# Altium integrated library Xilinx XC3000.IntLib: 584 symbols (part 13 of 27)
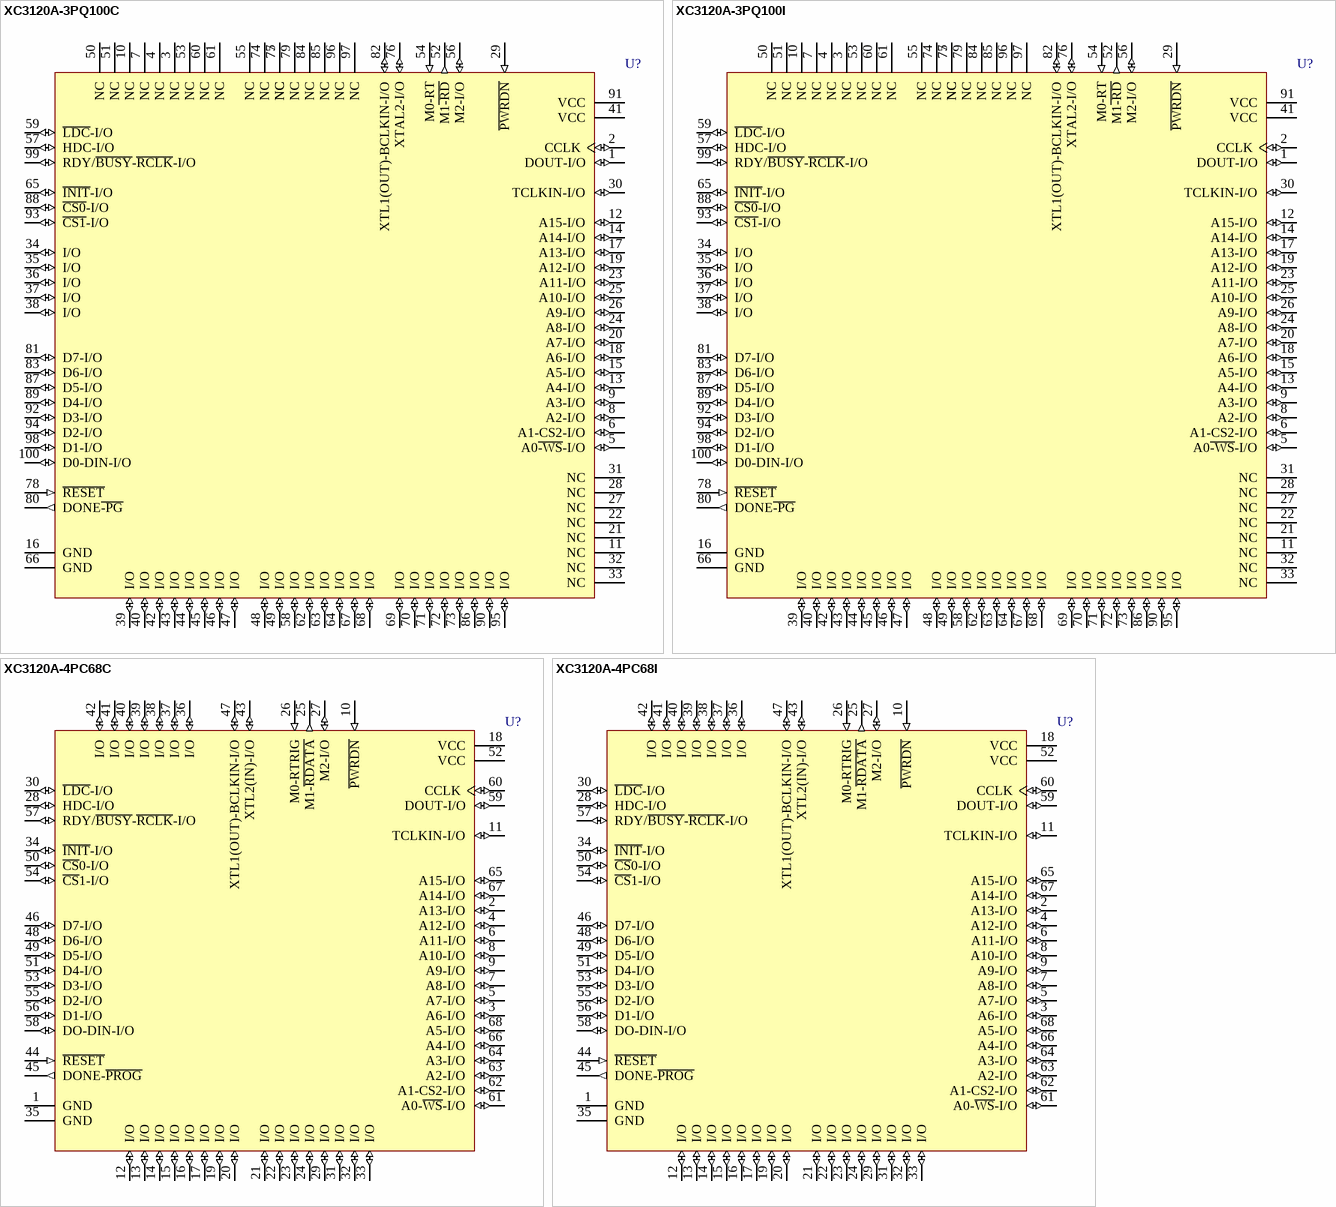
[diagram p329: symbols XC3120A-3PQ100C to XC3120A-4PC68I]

## XC3120A-4PC68C
designator U?
Logic Cell Array with 64 CLBs, with 58 I/O Pins, 68-Pin PLCC, Commercial Grade; ComponentAvailability: Not for New Design
footprint PC68_N (Leaded Chip Carrier, 68-Leads, Body 24x24mm, Pitch 1.27mm, IPC Medium Density)
footprint PC68_L (Leaded Chip Carrier, 68-Leads, Body 24x24mm, Pitch 1.27mm, IPC High Density)
footprint PC68_M (Leaded Chip Carrier, 68-Leads, Body 24x24mm, Pitch 1.27mm, IPC Low Density)
3D model XC3120A-PC68 (68-Pin Plastic Leaded Chip Carrier (PC68))
pins: 1 GND (power), 2 A13-I/O (io), 3 A6-I/O (io), 4 A12-I/O (io), 5 A7-I/O (io), 6 A11-I/O (io), 7 A8-I/O (io), 8 A10-I/O (io), 9 A9-I/O (io), 10 ~{PWRDN} (in), 11 TCLKIN-I/O (io), 12 I/O (io), 13 I/O (io), 14 I/O (io), 15 I/O (io), 16 I/O (io), 17 I/O (io), 18 VCC (power), 19 I/O (io), 20 I/O (io), 21 I/O (io), 22 I/O (io), 23 I/O (io), 24 I/O (io), 25 M1-~{RDATA} (out), 26 M0-RTRIG (in), 27 M2-I/O (io), 28 HDC-I/O (io), 29 I/O (io), 30 ~{LDC}-I/O (io), 31 I/O (io), 32 I/O (io), 33 I/O (io), 34 ~{INIT}-I/O (io), 35 GND (power), 36 I/O (io), 37 I/O (io), 38 I/O (io), 39 I/O (io), 40 I/O (io), 41 I/O (io), 42 I/O (io), 43 XTL2(IN)-I/O (io), 44 ~{RESET} (in), 45 DONE-~{PROG} (out), 46 D7-I/O (io), 47 XTL1(OUT)-BCLKIN-I/O (io), 48 D6-I/O (io), 49 D5-I/O (io), 50 ~{CS}0-I/O (io), 51 D4-I/O (io), 52 VCC (power), 53 D3-I/O (io), 54 ~{CS}1-I/O (io), 55 D2-I/O (io), 56 D1-I/O (io), 57 RDY/~{BUSY}-~{RCLK}-I/O (io), 58 DO-DIN-I/O (io), 59 DOUT-I/O (io), 60 CCLK (io), 61 A0-~{WS}-I/O (io), 62 A1-CS2-I/O (io), 63 A2-I/O (io), 64 A3-I/O (io), 65 A15-I/O (io), 66 A4-I/O (io), 67 A14-I/O (io), 68 A5-I/O (io)

## XC3120A-4PC68I
designator U?
Logic Cell Array with 64 CLBs, with 58 I/O Pins, 68-Pin PLCC, Industrial Grade; ComponentAvailability: Not for New Design
footprint PC68_N (Leaded Chip Carrier, 68-Leads, Body 24x24mm, Pitch 1.27mm, IPC Medium Density)
footprint PC68_L (Leaded Chip Carrier, 68-Leads, Body 24x24mm, Pitch 1.27mm, IPC High Density)
footprint PC68_M (Leaded Chip Carrier, 68-Leads, Body 24x24mm, Pitch 1.27mm, IPC Low Density)
3D model XC3120A-PC68 (68-Pin Plastic Leaded Chip Carrier (PC68))
pins: 1 GND (power), 2 A13-I/O (io), 3 A6-I/O (io), 4 A12-I/O (io), 5 A7-I/O (io), 6 A11-I/O (io), 7 A8-I/O (io), 8 A10-I/O (io), 9 A9-I/O (io), 10 ~{PWRDN} (in), 11 TCLKIN-I/O (io), 12 I/O (io), 13 I/O (io), 14 I/O (io), 15 I/O (io), 16 I/O (io), 17 I/O (io), 18 VCC (power), 19 I/O (io), 20 I/O (io), 21 I/O (io), 22 I/O (io), 23 I/O (io), 24 I/O (io), 25 M1-~{RDATA} (out), 26 M0-RTRIG (in), 27 M2-I/O (io), 28 HDC-I/O (io), 29 I/O (io), 30 ~{LDC}-I/O (io), 31 I/O (io), 32 I/O (io), 33 I/O (io), 34 ~{INIT}-I/O (io), 35 GND (power), 36 I/O (io), 37 I/O (io), 38 I/O (io), 39 I/O (io), 40 I/O (io), 41 I/O (io), 42 I/O (io), 43 XTL2(IN)-I/O (io), 44 ~{RESET} (in), 45 DONE-~{PROG} (out), 46 D7-I/O (io), 47 XTL1(OUT)-BCLKIN-I/O (io), 48 D6-I/O (io), 49 D5-I/O (io), 50 ~{CS}0-I/O (io), 51 D4-I/O (io), 52 VCC (power), 53 D3-I/O (io), 54 ~{CS}1-I/O (io), 55 D2-I/O (io), 56 D1-I/O (io), 57 RDY/~{BUSY}-~{RCLK}-I/O (io), 58 DO-DIN-I/O (io), 59 DOUT-I/O (io), 60 CCLK (io), 61 A0-~{WS}-I/O (io), 62 A1-CS2-I/O (io), 63 A2-I/O (io), 64 A3-I/O (io), 65 A15-I/O (io), 66 A4-I/O (io), 67 A14-I/O (io), 68 A5-I/O (io)

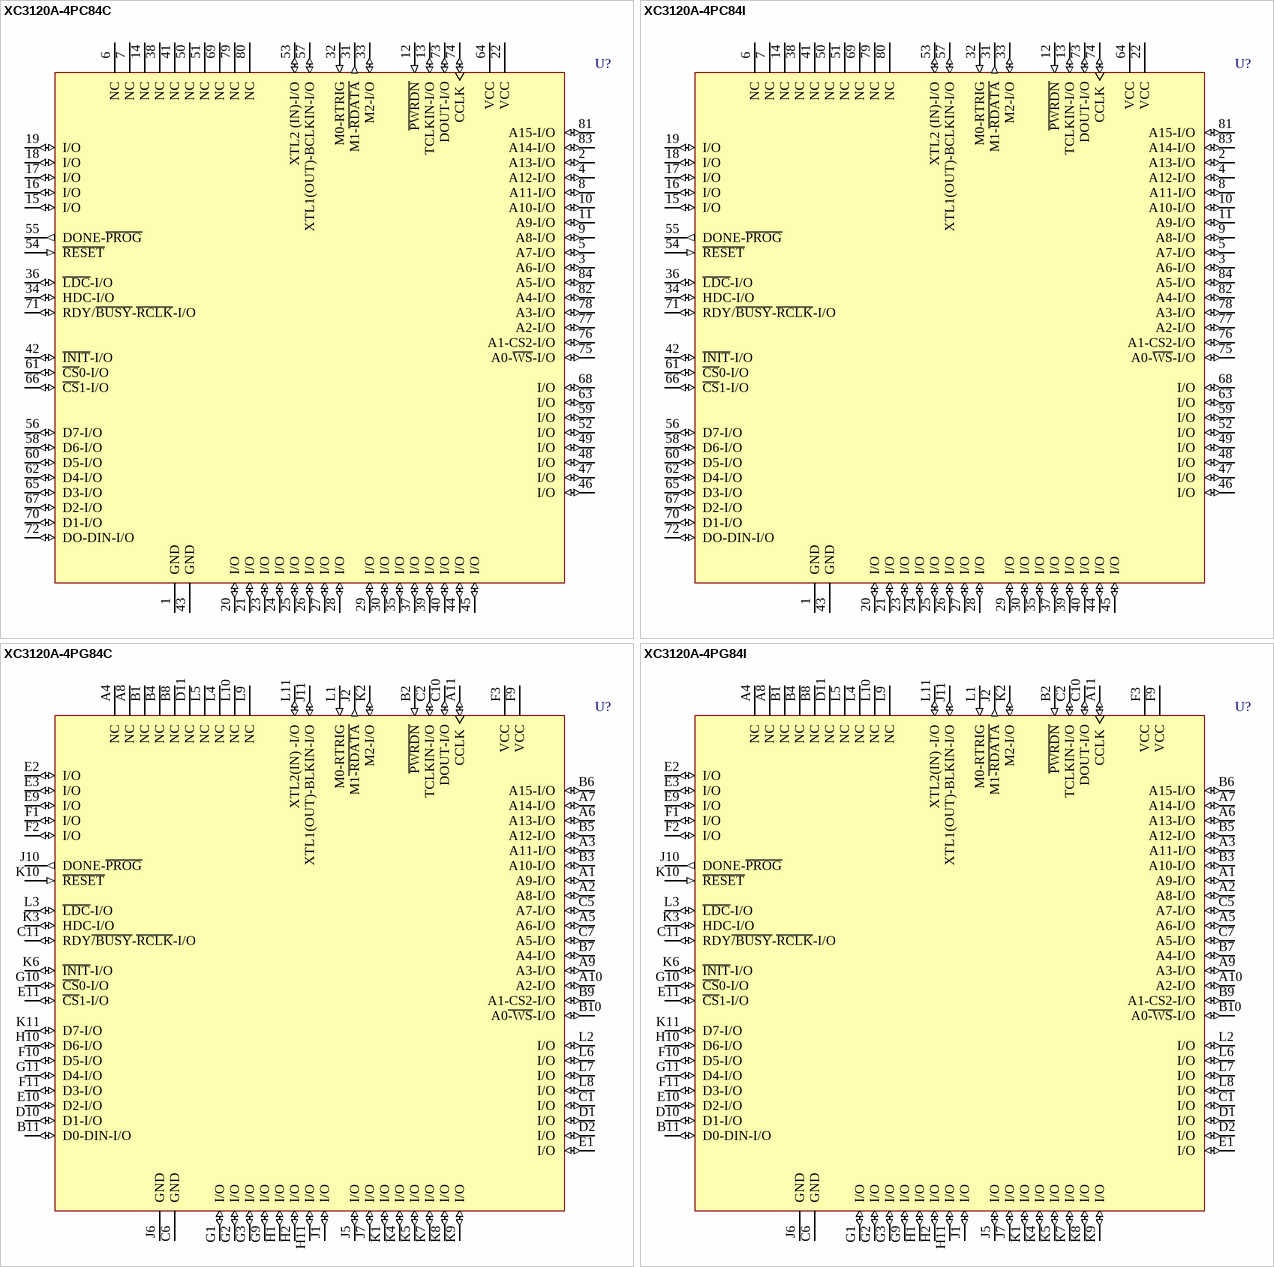
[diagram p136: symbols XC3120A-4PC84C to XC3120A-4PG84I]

## XC3120A-4PC84C
designator U?
Logic Cell Array with 64 CLBs, with 64 I/O Pins, 84-Pin PLCC, Commercial Grade; ComponentAvailability: Not for New Design
footprint PC84_N (Leaded Chip Carrier, 84-Leads, Body 29.3x29.3mm, Pitch 1.27mm, IPC Medium Density)
footprint PC84_L (Leaded Chip Carrier, 84-Leads, Body 29.3x29.3mm, Pitch 1.27mm, IPC High Density)
footprint PC84_M (Leaded Chip Carrier, 84-Leads, Body 29.3x29.3mm, Pitch 1.27mm, IPC Low Density)
3D model XC3120A-PC84 (84-Pin Plastic Leaded Chip Carrier (PC84))
pins: 1 GND (power), 2 A13-I/O (io), 3 A6-I/O (io), 4 A12-I/O (io), 5 A7-I/O (io), 6 NC, 7 NC, 8 A11-I/O (io), 9 A8-I/O (io), 10 A10-I/O (io), 11 A9-I/O (io), 12 ~{PWRDN} (in), 13 TCLKIN-I/O (io), 14 NC, 15 I/O (io), 16 I/O (io), 17 I/O (io), 18 I/O (io), 19 I/O (io), 20 I/O (io), 21 I/O (io), 22 VCC (power), 23 I/O (io), 24 I/O (io), 25 I/O (io), 26 I/O (io), 27 I/O (io), 28 I/O (io), 29 I/O (io), 30 I/O (io), 31 M1-~{RDATA} (out), 32 M0-RTRIG (in), 33 M2-I/O (io), 34 HDC-I/O (io), 35 I/O (io), 36 ~{LDC}-I/O (io), 37 I/O (io), 38 NC, 39 I/O (io), 40 I/O (io), 41 NC, 42 ~{INIT}-I/O (io), 43 GND (power), 44 I/O (io), 45 I/O (io), 46 I/O (io), 47 I/O (io), 48 I/O (io), 49 I/O (io), 50 NC, 51 NC, 52 I/O (io), 53 XTL2 (IN)-I/O (io), 54 ~{RESET} (in), 55 DONE-~{PROG} (out), 56 D7-I/O (io), 57 XTL1(OUT)-BCLKIN-I/O (io), 58 D6-I/O (io), 59 I/O (io), 60 D5-I/O (io), 61 ~{CS}0-I/O (io), 62 D4-I/O (io), 63 I/O (io), 64 VCC (power), 65 D3-I/O (io), 66 ~{CS}1-I/O (io), 67 D2-I/O (io), 68 I/O (io), 69 NC, 70 D1-I/O (io), 71 RDY/~{BUSY}-~{RCLK}-I/O (io), 72 DO-DIN-I/O (io), 73 DOUT-I/O (io), 74 CCLK (io), 75 A0-~{WS}-I/O (io), 76 A1-CS2-I/O (io), 77 A2-I/O (io), 78 A3-I/O (io), 79 NC, 80 NC, 81 A15-I/O (io), 82 A4-I/O (io), 83 A14-I/O (io), 84 A5-I/O (io)

## XC3120A-4PC84I
designator U?
Logic Cell Array with 64 CLBs, with 64 I/O Pins, 84-Pin PLCC, Industrial Grade; ComponentAvailability: Not for New Design
footprint PC84_N (Leaded Chip Carrier, 84-Leads, Body 29.3x29.3mm, Pitch 1.27mm, IPC Medium Density)
footprint PC84_L (Leaded Chip Carrier, 84-Leads, Body 29.3x29.3mm, Pitch 1.27mm, IPC High Density)
footprint PC84_M (Leaded Chip Carrier, 84-Leads, Body 29.3x29.3mm, Pitch 1.27mm, IPC Low Density)
3D model XC3120A-PC84 (84-Pin Plastic Leaded Chip Carrier (PC84))
pins: 1 GND (power), 2 A13-I/O (io), 3 A6-I/O (io), 4 A12-I/O (io), 5 A7-I/O (io), 6 NC, 7 NC, 8 A11-I/O (io), 9 A8-I/O (io), 10 A10-I/O (io), 11 A9-I/O (io), 12 ~{PWRDN} (in), 13 TCLKIN-I/O (io), 14 NC, 15 I/O (io), 16 I/O (io), 17 I/O (io), 18 I/O (io), 19 I/O (io), 20 I/O (io), 21 I/O (io), 22 VCC (power), 23 I/O (io), 24 I/O (io), 25 I/O (io), 26 I/O (io), 27 I/O (io), 28 I/O (io), 29 I/O (io), 30 I/O (io), 31 M1-~{RDATA} (out), 32 M0-RTRIG (in), 33 M2-I/O (io), 34 HDC-I/O (io), 35 I/O (io), 36 ~{LDC}-I/O (io), 37 I/O (io), 38 NC, 39 I/O (io), 40 I/O (io), 41 NC, 42 ~{INIT}-I/O (io), 43 GND (power), 44 I/O (io), 45 I/O (io), 46 I/O (io), 47 I/O (io), 48 I/O (io), 49 I/O (io), 50 NC, 51 NC, 52 I/O (io), 53 XTL2 (IN)-I/O (io), 54 ~{RESET} (in), 55 DONE-~{PROG} (out), 56 D7-I/O (io), 57 XTL1(OUT)-BCLKIN-I/O (io), 58 D6-I/O (io), 59 I/O (io), 60 D5-I/O (io), 61 ~{CS}0-I/O (io), 62 D4-I/O (io), 63 I/O (io), 64 VCC (power), 65 D3-I/O (io), 66 ~{CS}1-I/O (io), 67 D2-I/O (io), 68 I/O (io), 69 NC, 70 D1-I/O (io), 71 RDY/~{BUSY}-~{RCLK}-I/O (io), 72 DO-DIN-I/O (io), 73 DOUT-I/O (io), 74 CCLK (io), 75 A0-~{WS}-I/O (io), 76 A1-CS2-I/O (io), 77 A2-I/O (io), 78 A3-I/O (io), 79 NC, 80 NC, 81 A15-I/O (io), 82 A4-I/O (io), 83 A14-I/O (io), 84 A5-I/O (io)

## XC3120A-4PG84C
designator U?
Logic Cell Array with 64 CLBs, with 64 I/O Pins, 84-Pin PGA, Commercial Grade; ComponentAvailability: Not for New Design
footprint PG84 (PGA, 85-Leads, Body 28x28mm, Pitch 2.54mm)
3D model XC3120A-PG84 (84-Pin Ceramic Pin Grid Array (PG84))
pins: A1 A9-I/O (io), A2 A8-I/O (io), A3 A11-I/O (io), A4 NC, A5 A6-I/O (io), A6 A13-I/O (io), A7 A14-I/O (io), A8 NC, A9 A3-I/O (io), A10 A2-I/O (io), A11 CCLK (io), B1 NC, B2 ~{PWRDN} (in), B3 A10-I/O (io), B4 NC, B5 A12-I/O (io), B6 A15-I/O (io), B7 A4-I/O (io), B8 NC, B9 A1-CS2-I/O (io), B10 A0~{-WS}-I/O (io), B11 D0-DIN-I/O (io), C1 I/O (io), C2 TCLKIN-I/O (io), C5 A7-I/O (io), C6 GND (power), C7 A5-I/O (io), C10 DOUT-I/O (io), C11 RDY~{/BUSY}-~{RCLK}-I/O (io), D1 I/O (io), D2 I/O (io), D10 D1-I/O (io), D11 NC, E1 I/O (io), E2 I/O (io), E3 I/O (io), E9 I/O (io), E10 D2-I/O (io), E11 ~{CS}1-I/O (io), F1 I/O (io), F2 I/O (io), F3 VCC (power), F9 VCC (power), F10 D5-I/O (io), F11 D3-I/O (io), G1 I/O (io), G2 I/O (io), G3 I/O (io), G9 I/O (io), G10 ~{CS}0-I/O (io), G11 D4-I/O (io), H1 I/O (io), H2 I/O (io), H10 D6-I/O (io), H11 I/O (io), J1 I/O (io), J2 M1~{-RDATA} (out), J5 I/O (io), J6 GND (power), J7 I/O (io), J10 DONE-~{PROG} (out), J11 XTL1(OUT)-BLKIN-I/O (io), K1 I/O (io), K2 M2-I/O (io), K3 HDC-I/O (io), K4 I/O (io), K5 I/O (io), K6 ~{INIT}-I/O (io), K7 I/O (io), K8 I/O (io), K9 I/O (io), K10 ~{RESET} (in), K11 D7-I/O (io), L1 M0-RTRIG (in), L2 I/O (io), L3 ~{LDC}-I/O (io), L4 NC, L5 NC, L6 I/O (io), L7 I/O (io), L8 I/O (io), L9 NC, L10 NC, L11 XTL2(IN) -I/O (io)

## XC3120A-4PG84I
designator U?
Logic Cell Array with 64 CLBs, with 64 I/O Pins, 84-Pin PGA, Industrial Grade; ComponentAvailability: Not for New Design
footprint PG84 (PGA, 85-Leads, Body 28x28mm, Pitch 2.54mm)
3D model XC3120A-PG84 (84-Pin Ceramic Pin Grid Array (PG84))
pins: A1 A9-I/O (io), A2 A8-I/O (io), A3 A11-I/O (io), A4 NC, A5 A6-I/O (io), A6 A13-I/O (io), A7 A14-I/O (io), A8 NC, A9 A3-I/O (io), A10 A2-I/O (io), A11 CCLK (io), B1 NC, B2 ~{PWRDN} (in), B3 A10-I/O (io), B4 NC, B5 A12-I/O (io), B6 A15-I/O (io), B7 A4-I/O (io), B8 NC, B9 A1-CS2-I/O (io), B10 A0~{-WS}-I/O (io), B11 D0-DIN-I/O (io), C1 I/O (io), C2 TCLKIN-I/O (io), C5 A7-I/O (io), C6 GND (power), C7 A5-I/O (io), C10 DOUT-I/O (io), C11 RDY~{/BUSY}-~{RCLK}-I/O (io), D1 I/O (io), D2 I/O (io), D10 D1-I/O (io), D11 NC, E1 I/O (io), E2 I/O (io), E3 I/O (io), E9 I/O (io), E10 D2-I/O (io), E11 ~{CS}1-I/O (io), F1 I/O (io), F2 I/O (io), F3 VCC (power), F9 VCC (power), F10 D5-I/O (io), F11 D3-I/O (io), G1 I/O (io), G2 I/O (io), G3 I/O (io), G9 I/O (io), G10 ~{CS}0-I/O (io), G11 D4-I/O (io), H1 I/O (io), H2 I/O (io), H10 D6-I/O (io), H11 I/O (io), J1 I/O (io), J2 M1~{-RDATA} (out), J5 I/O (io), J6 GND (power), J7 I/O (io), J10 DONE-~{PROG} (out), J11 XTL1(OUT)-BLKIN-I/O (io), K1 I/O (io), K2 M2-I/O (io), K3 HDC-I/O (io), K4 I/O (io), K5 I/O (io), K6 ~{INIT}-I/O (io), K7 I/O (io), K8 I/O (io), K9 I/O (io), K10 ~{RESET} (in), K11 D7-I/O (io), L1 M0-RTRIG (in), L2 I/O (io), L3 ~{LDC}-I/O (io), L4 NC, L5 NC, L6 I/O (io), L7 I/O (io), L8 I/O (io), L9 NC, L10 NC, L11 XTL2(IN) -I/O (io)

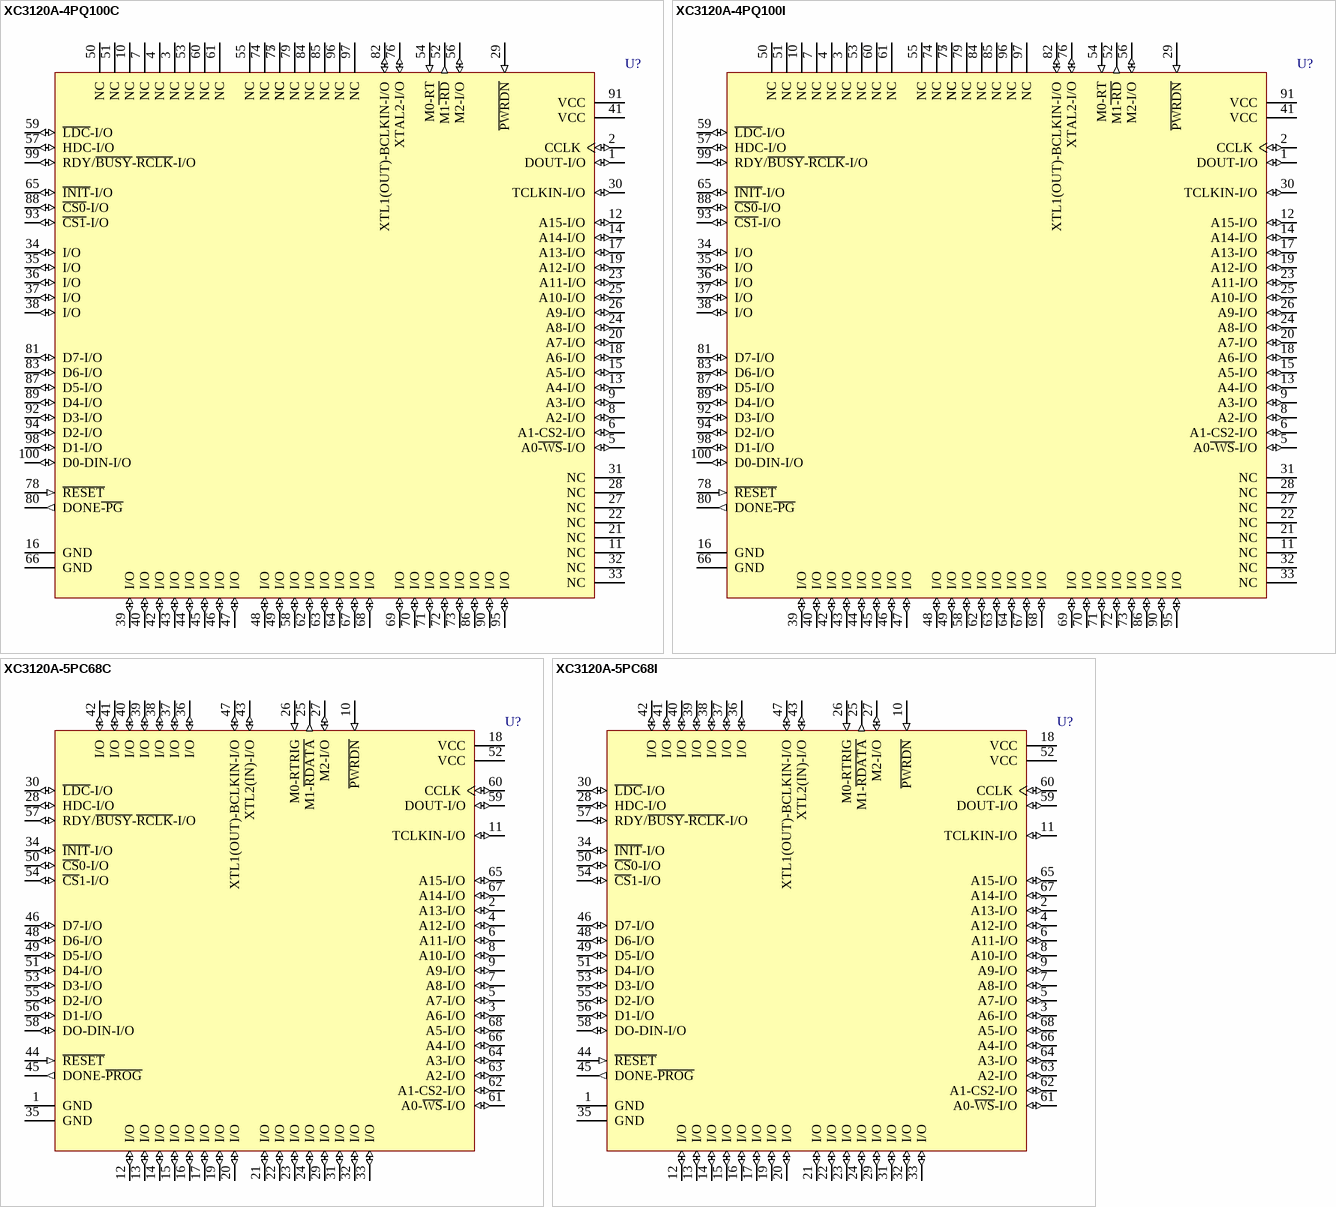
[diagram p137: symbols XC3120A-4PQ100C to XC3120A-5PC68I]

## XC3120A-4PQ100C
designator U?
Logic Cell Array with 64 CLBs, with 64 I/O Pins, 100-Pin PQFP, Commercial Grade; ComponentAvailability: Not for New Design
footprint PQ100_N (QFP, 100-Leads, Body 20x14mm, Pitch 0.65mm, IPC Medium Density)
footprint PQ100_L (QFP, 100-Leads, Body 20x14mm, Pitch 0.65mm, IPC High Density)
footprint PQ100_M (QFP, 100-Leads, Body 20x14mm, Pitch 0.65mm, IPC Low Density)
3D model XC3120A-PQ100 (100-Pin Plastic Quad Flat Pack (PQ100))
pins: 1 DOUT-I/O (io), 2 CCLK (io), 3 NC, 4 NC, 5 A0~{-WS}-I/O (io), 6 A1-CS2-I/O (io), 7 NC, 8 A2-I/O (io), 9 A3-I/O (io), 10 NC, 11 NC, 12 A15-I/O (io), 13 A4-I/O (io), 14 A14-I/O (io), 15 A5-I/O (io), 16 GND (power), 17 A13-I/O (io), 18 A6-I/O (io), 19 A12-I/O (io), 20 A7-I/O (io), 21 NC, 22 NC, 23 A11-I/O (io), 24 A8-I/O (io), 25 A10-I/O (io), 26 A9-I/O (io), 27 NC, 28 NC, 29 ~{PWRDN} (in), 30 TCLKIN-I/O (io), 31 NC, 32 NC, 33 NC, 34 I/O (io), 35 I/O (io), 36 I/O (io), 37 I/O (io), 38 I/O (io), 39 I/O (io), 40 I/O (io), 41 VCC (power), 42 I/O (io), 43 I/O (io), 44 I/O (io), 45 I/O (io), 46 I/O (io), 47 I/O (io), 48 I/O (io), 49 I/O (io), 50 NC, 51 NC, 52 M1~{-RD} (out), 53 NC, 54 M0-RT (in), 55 NC, 56 M2-I/O (io), 57 HDC-I/O (io), 58 I/O (io), 59 ~{LDC}-I/O (io), 60 NC, 61 NC, 62 I/O (io), 63 I/O (io), 64 I/O (io), 65 ~{INIT}-I/O (io), 66 GND (power), 67 I/O (io), 68 I/O (io), 69 I/O (io), 70 I/O (io), 71 I/O (io), 72 I/O (io), 73 I/O (io), 74 NC, 75 NC, 76 XTAL2-I/O (io), 77 NC, 78 ~{RESET} (in), 79 NC, 80 DONE~{-PG} (out), 81 D7-I/O (io), 82 XTL1(OUT)-BCLKIN-I/O (io), 83 D6-I/O (io), 84 NC, 85 NC, 86 I/O (io), 87 D5-I/O (io), 88 ~{CS0}-I/O (io), 89 D4-I/O (io), 90 I/O (io), 91 VCC (power), 92 D3-I/O (io), 93 ~{CS1}-I/O (io), 94 D2-I/O (io), 95 I/O (io), 96 NC, 97 NC, 98 D1-I/O (io), 99 RDY/~{BUSY}-~{RCLK}-I/O (io), 100 D0-DIN-I/O (io)

## XC3120A-4PQ100I
designator U?
Logic Cell Array with 64 CLBs, with 64 I/O Pins, 100-Pin PQFP, Industrial Grade; ComponentAvailability: Not for New Design
footprint PQ100_N (QFP, 100-Leads, Body 20x14mm, Pitch 0.65mm, IPC Medium Density)
footprint PQ100_L (QFP, 100-Leads, Body 20x14mm, Pitch 0.65mm, IPC High Density)
footprint PQ100_M (QFP, 100-Leads, Body 20x14mm, Pitch 0.65mm, IPC Low Density)
3D model XC3120A-PQ100 (100-Pin Plastic Quad Flat Pack (PQ100))
pins: 1 DOUT-I/O (io), 2 CCLK (io), 3 NC, 4 NC, 5 A0~{-WS}-I/O (io), 6 A1-CS2-I/O (io), 7 NC, 8 A2-I/O (io), 9 A3-I/O (io), 10 NC, 11 NC, 12 A15-I/O (io), 13 A4-I/O (io), 14 A14-I/O (io), 15 A5-I/O (io), 16 GND (power), 17 A13-I/O (io), 18 A6-I/O (io), 19 A12-I/O (io), 20 A7-I/O (io), 21 NC, 22 NC, 23 A11-I/O (io), 24 A8-I/O (io), 25 A10-I/O (io), 26 A9-I/O (io), 27 NC, 28 NC, 29 ~{PWRDN} (in), 30 TCLKIN-I/O (io), 31 NC, 32 NC, 33 NC, 34 I/O (io), 35 I/O (io), 36 I/O (io), 37 I/O (io), 38 I/O (io), 39 I/O (io), 40 I/O (io), 41 VCC (power), 42 I/O (io), 43 I/O (io), 44 I/O (io), 45 I/O (io), 46 I/O (io), 47 I/O (io), 48 I/O (io), 49 I/O (io), 50 NC, 51 NC, 52 M1~{-RD} (out), 53 NC, 54 M0-RT (in), 55 NC, 56 M2-I/O (io), 57 HDC-I/O (io), 58 I/O (io), 59 ~{LDC}-I/O (io), 60 NC, 61 NC, 62 I/O (io), 63 I/O (io), 64 I/O (io), 65 ~{INIT}-I/O (io), 66 GND (power), 67 I/O (io), 68 I/O (io), 69 I/O (io), 70 I/O (io), 71 I/O (io), 72 I/O (io), 73 I/O (io), 74 NC, 75 NC, 76 XTAL2-I/O (io), 77 NC, 78 ~{RESET} (in), 79 NC, 80 DONE~{-PG} (out), 81 D7-I/O (io), 82 XTL1(OUT)-BCLKIN-I/O (io), 83 D6-I/O (io), 84 NC, 85 NC, 86 I/O (io), 87 D5-I/O (io), 88 ~{CS0}-I/O (io), 89 D4-I/O (io), 90 I/O (io), 91 VCC (power), 92 D3-I/O (io), 93 ~{CS1}-I/O (io), 94 D2-I/O (io), 95 I/O (io), 96 NC, 97 NC, 98 D1-I/O (io), 99 RDY/~{BUSY}-~{RCLK}-I/O (io), 100 D0-DIN-I/O (io)

## XC3120A-5PC68C
designator U?
Logic Cell Array with 64 CLBs, with 58 I/O Pins, 68-Pin PLCC, Commercial Grade; ComponentAvailability: Not for New Design
footprint PC68_N (Leaded Chip Carrier, 68-Leads, Body 24x24mm, Pitch 1.27mm, IPC Medium Density)
footprint PC68_L (Leaded Chip Carrier, 68-Leads, Body 24x24mm, Pitch 1.27mm, IPC High Density)
footprint PC68_M (Leaded Chip Carrier, 68-Leads, Body 24x24mm, Pitch 1.27mm, IPC Low Density)
3D model XC3120A-PC68 (68-Pin Plastic Leaded Chip Carrier (PC68))
pins: 1 GND (power), 2 A13-I/O (io), 3 A6-I/O (io), 4 A12-I/O (io), 5 A7-I/O (io), 6 A11-I/O (io), 7 A8-I/O (io), 8 A10-I/O (io), 9 A9-I/O (io), 10 ~{PWRDN} (in), 11 TCLKIN-I/O (io), 12 I/O (io), 13 I/O (io), 14 I/O (io), 15 I/O (io), 16 I/O (io), 17 I/O (io), 18 VCC (power), 19 I/O (io), 20 I/O (io), 21 I/O (io), 22 I/O (io), 23 I/O (io), 24 I/O (io), 25 M1-~{RDATA} (out), 26 M0-RTRIG (in), 27 M2-I/O (io), 28 HDC-I/O (io), 29 I/O (io), 30 ~{LDC}-I/O (io), 31 I/O (io), 32 I/O (io), 33 I/O (io), 34 ~{INIT}-I/O (io), 35 GND (power), 36 I/O (io), 37 I/O (io), 38 I/O (io), 39 I/O (io), 40 I/O (io), 41 I/O (io), 42 I/O (io), 43 XTL2(IN)-I/O (io), 44 ~{RESET} (in), 45 DONE-~{PROG} (out), 46 D7-I/O (io), 47 XTL1(OUT)-BCLKIN-I/O (io), 48 D6-I/O (io), 49 D5-I/O (io), 50 ~{CS}0-I/O (io), 51 D4-I/O (io), 52 VCC (power), 53 D3-I/O (io), 54 ~{CS}1-I/O (io), 55 D2-I/O (io), 56 D1-I/O (io), 57 RDY/~{BUSY}-~{RCLK}-I/O (io), 58 DO-DIN-I/O (io), 59 DOUT-I/O (io), 60 CCLK (io), 61 A0-~{WS}-I/O (io), 62 A1-CS2-I/O (io), 63 A2-I/O (io), 64 A3-I/O (io), 65 A15-I/O (io), 66 A4-I/O (io), 67 A14-I/O (io), 68 A5-I/O (io)

## XC3120A-5PC68I
designator U?
Logic Cell Array with 64 CLBs, with 58 I/O Pins, 68-Pin PLCC, Industrial Grade; ComponentAvailability: Not for New Design
footprint PC68_N (Leaded Chip Carrier, 68-Leads, Body 24x24mm, Pitch 1.27mm, IPC Medium Density)
footprint PC68_L (Leaded Chip Carrier, 68-Leads, Body 24x24mm, Pitch 1.27mm, IPC High Density)
footprint PC68_M (Leaded Chip Carrier, 68-Leads, Body 24x24mm, Pitch 1.27mm, IPC Low Density)
3D model XC3120A-PC68 (68-Pin Plastic Leaded Chip Carrier (PC68))
pins: 1 GND (power), 2 A13-I/O (io), 3 A6-I/O (io), 4 A12-I/O (io), 5 A7-I/O (io), 6 A11-I/O (io), 7 A8-I/O (io), 8 A10-I/O (io), 9 A9-I/O (io), 10 ~{PWRDN} (in), 11 TCLKIN-I/O (io), 12 I/O (io), 13 I/O (io), 14 I/O (io), 15 I/O (io), 16 I/O (io), 17 I/O (io), 18 VCC (power), 19 I/O (io), 20 I/O (io), 21 I/O (io), 22 I/O (io), 23 I/O (io), 24 I/O (io), 25 M1-~{RDATA} (out), 26 M0-RTRIG (in), 27 M2-I/O (io), 28 HDC-I/O (io), 29 I/O (io), 30 ~{LDC}-I/O (io), 31 I/O (io), 32 I/O (io), 33 I/O (io), 34 ~{INIT}-I/O (io), 35 GND (power), 36 I/O (io), 37 I/O (io), 38 I/O (io), 39 I/O (io), 40 I/O (io), 41 I/O (io), 42 I/O (io), 43 XTL2(IN)-I/O (io), 44 ~{RESET} (in), 45 DONE-~{PROG} (out), 46 D7-I/O (io), 47 XTL1(OUT)-BCLKIN-I/O (io), 48 D6-I/O (io), 49 D5-I/O (io), 50 ~{CS}0-I/O (io), 51 D4-I/O (io), 52 VCC (power), 53 D3-I/O (io), 54 ~{CS}1-I/O (io), 55 D2-I/O (io), 56 D1-I/O (io), 57 RDY/~{BUSY}-~{RCLK}-I/O (io), 58 DO-DIN-I/O (io), 59 DOUT-I/O (io), 60 CCLK (io), 61 A0-~{WS}-I/O (io), 62 A1-CS2-I/O (io), 63 A2-I/O (io), 64 A3-I/O (io), 65 A15-I/O (io), 66 A4-I/O (io), 67 A14-I/O (io), 68 A5-I/O (io)

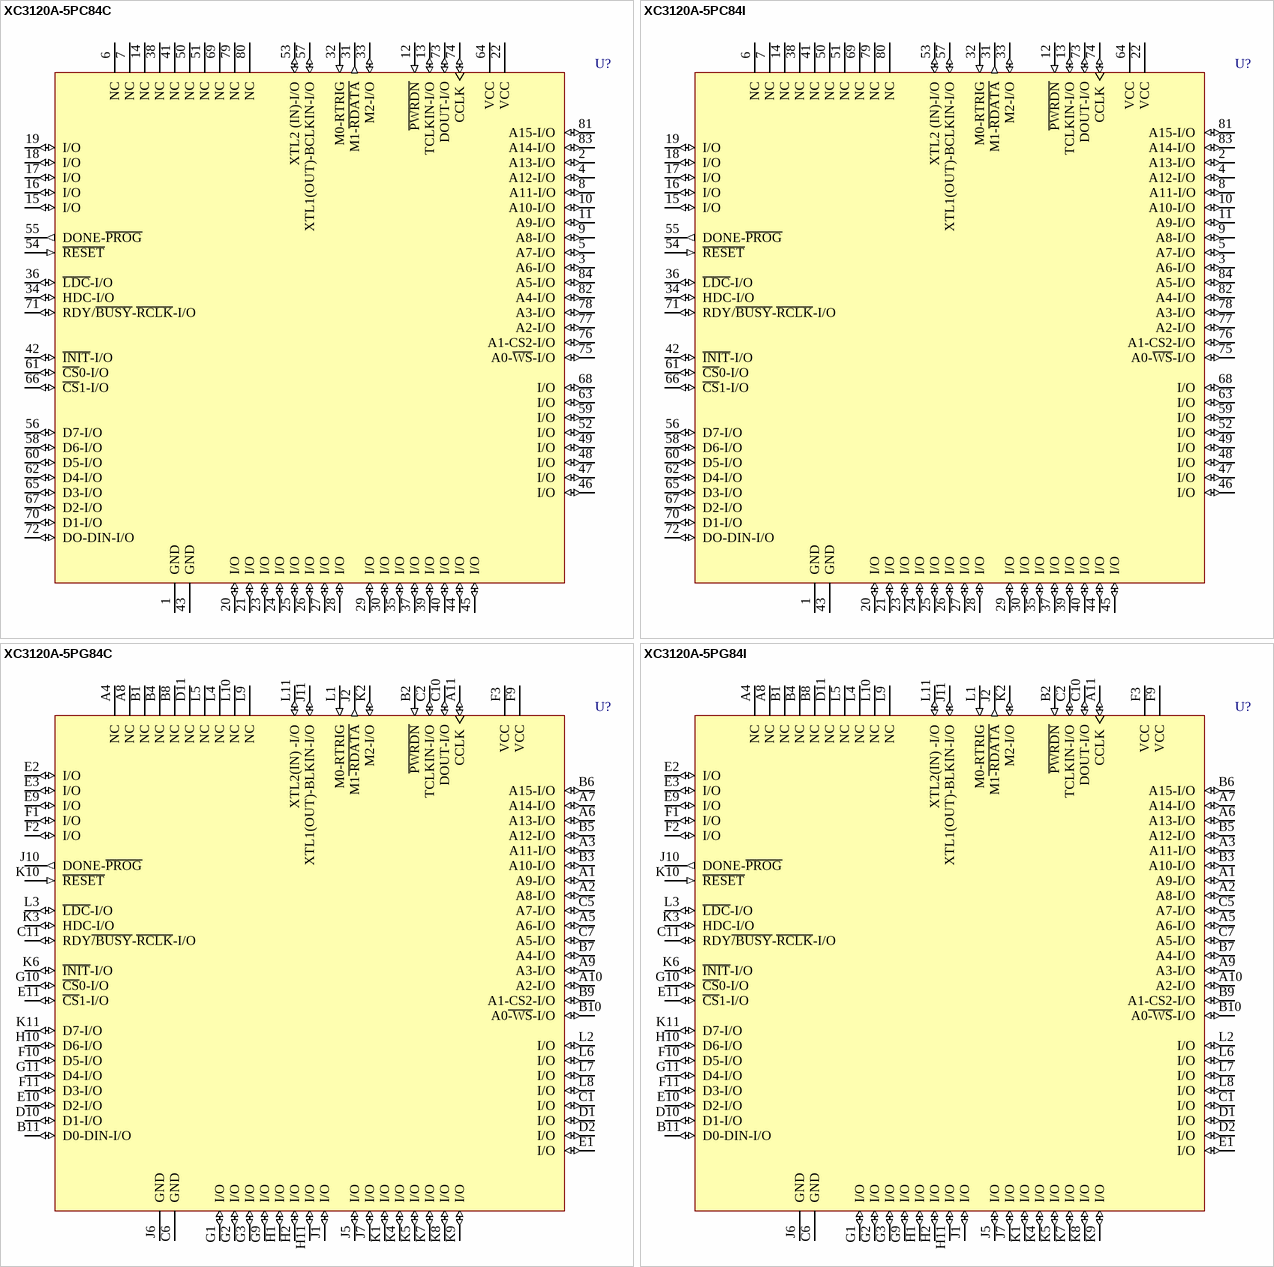
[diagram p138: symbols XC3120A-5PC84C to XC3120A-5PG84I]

## XC3120A-5PC84C
designator U?
Logic Cell Array with 64 CLBs, with 64 I/O Pins, 84-Pin PLCC, Commercial Grade; ComponentAvailability: Not for New Design
footprint PC84_N (Leaded Chip Carrier, 84-Leads, Body 29.3x29.3mm, Pitch 1.27mm, IPC Medium Density)
footprint PC84_L (Leaded Chip Carrier, 84-Leads, Body 29.3x29.3mm, Pitch 1.27mm, IPC High Density)
footprint PC84_M (Leaded Chip Carrier, 84-Leads, Body 29.3x29.3mm, Pitch 1.27mm, IPC Low Density)
3D model XC3120A-PC84 (84-Pin Plastic Leaded Chip Carrier (PC84))
pins: 1 GND (power), 2 A13-I/O (io), 3 A6-I/O (io), 4 A12-I/O (io), 5 A7-I/O (io), 6 NC, 7 NC, 8 A11-I/O (io), 9 A8-I/O (io), 10 A10-I/O (io), 11 A9-I/O (io), 12 ~{PWRDN} (in), 13 TCLKIN-I/O (io), 14 NC, 15 I/O (io), 16 I/O (io), 17 I/O (io), 18 I/O (io), 19 I/O (io), 20 I/O (io), 21 I/O (io), 22 VCC (power), 23 I/O (io), 24 I/O (io), 25 I/O (io), 26 I/O (io), 27 I/O (io), 28 I/O (io), 29 I/O (io), 30 I/O (io), 31 M1-~{RDATA} (out), 32 M0-RTRIG (in), 33 M2-I/O (io), 34 HDC-I/O (io), 35 I/O (io), 36 ~{LDC}-I/O (io), 37 I/O (io), 38 NC, 39 I/O (io), 40 I/O (io), 41 NC, 42 ~{INIT}-I/O (io), 43 GND (power), 44 I/O (io), 45 I/O (io), 46 I/O (io), 47 I/O (io), 48 I/O (io), 49 I/O (io), 50 NC, 51 NC, 52 I/O (io), 53 XTL2 (IN)-I/O (io), 54 ~{RESET} (in), 55 DONE-~{PROG} (out), 56 D7-I/O (io), 57 XTL1(OUT)-BCLKIN-I/O (io), 58 D6-I/O (io), 59 I/O (io), 60 D5-I/O (io), 61 ~{CS}0-I/O (io), 62 D4-I/O (io), 63 I/O (io), 64 VCC (power), 65 D3-I/O (io), 66 ~{CS}1-I/O (io), 67 D2-I/O (io), 68 I/O (io), 69 NC, 70 D1-I/O (io), 71 RDY/~{BUSY}-~{RCLK}-I/O (io), 72 DO-DIN-I/O (io), 73 DOUT-I/O (io), 74 CCLK (io), 75 A0-~{WS}-I/O (io), 76 A1-CS2-I/O (io), 77 A2-I/O (io), 78 A3-I/O (io), 79 NC, 80 NC, 81 A15-I/O (io), 82 A4-I/O (io), 83 A14-I/O (io), 84 A5-I/O (io)

## XC3120A-5PC84I
designator U?
Logic Cell Array with 64 CLBs, with 64 I/O Pins, 84-Pin PLCC, Industrial Grade; ComponentAvailability: Not for New Design
footprint PC84_N (Leaded Chip Carrier, 84-Leads, Body 29.3x29.3mm, Pitch 1.27mm, IPC Medium Density)
footprint PC84_L (Leaded Chip Carrier, 84-Leads, Body 29.3x29.3mm, Pitch 1.27mm, IPC High Density)
footprint PC84_M (Leaded Chip Carrier, 84-Leads, Body 29.3x29.3mm, Pitch 1.27mm, IPC Low Density)
3D model XC3120A-PC84 (84-Pin Plastic Leaded Chip Carrier (PC84))
pins: 1 GND (power), 2 A13-I/O (io), 3 A6-I/O (io), 4 A12-I/O (io), 5 A7-I/O (io), 6 NC, 7 NC, 8 A11-I/O (io), 9 A8-I/O (io), 10 A10-I/O (io), 11 A9-I/O (io), 12 ~{PWRDN} (in), 13 TCLKIN-I/O (io), 14 NC, 15 I/O (io), 16 I/O (io), 17 I/O (io), 18 I/O (io), 19 I/O (io), 20 I/O (io), 21 I/O (io), 22 VCC (power), 23 I/O (io), 24 I/O (io), 25 I/O (io), 26 I/O (io), 27 I/O (io), 28 I/O (io), 29 I/O (io), 30 I/O (io), 31 M1-~{RDATA} (out), 32 M0-RTRIG (in), 33 M2-I/O (io), 34 HDC-I/O (io), 35 I/O (io), 36 ~{LDC}-I/O (io), 37 I/O (io), 38 NC, 39 I/O (io), 40 I/O (io), 41 NC, 42 ~{INIT}-I/O (io), 43 GND (power), 44 I/O (io), 45 I/O (io), 46 I/O (io), 47 I/O (io), 48 I/O (io), 49 I/O (io), 50 NC, 51 NC, 52 I/O (io), 53 XTL2 (IN)-I/O (io), 54 ~{RESET} (in), 55 DONE-~{PROG} (out), 56 D7-I/O (io), 57 XTL1(OUT)-BCLKIN-I/O (io), 58 D6-I/O (io), 59 I/O (io), 60 D5-I/O (io), 61 ~{CS}0-I/O (io), 62 D4-I/O (io), 63 I/O (io), 64 VCC (power), 65 D3-I/O (io), 66 ~{CS}1-I/O (io), 67 D2-I/O (io), 68 I/O (io), 69 NC, 70 D1-I/O (io), 71 RDY/~{BUSY}-~{RCLK}-I/O (io), 72 DO-DIN-I/O (io), 73 DOUT-I/O (io), 74 CCLK (io), 75 A0-~{WS}-I/O (io), 76 A1-CS2-I/O (io), 77 A2-I/O (io), 78 A3-I/O (io), 79 NC, 80 NC, 81 A15-I/O (io), 82 A4-I/O (io), 83 A14-I/O (io), 84 A5-I/O (io)

## XC3120A-5PG84C
designator U?
Logic Cell Array with 64 CLBs, with 64 I/O Pins, 84-Pin PGA, Commercial Grade; ComponentAvailability: Not for New Design
footprint PG84 (PGA, 85-Leads, Body 28x28mm, Pitch 2.54mm)
3D model XC3120A-PG84 (84-Pin Ceramic Pin Grid Array (PG84))
pins: A1 A9-I/O (io), A2 A8-I/O (io), A3 A11-I/O (io), A4 NC, A5 A6-I/O (io), A6 A13-I/O (io), A7 A14-I/O (io), A8 NC, A9 A3-I/O (io), A10 A2-I/O (io), A11 CCLK (io), B1 NC, B2 ~{PWRDN} (in), B3 A10-I/O (io), B4 NC, B5 A12-I/O (io), B6 A15-I/O (io), B7 A4-I/O (io), B8 NC, B9 A1-CS2-I/O (io), B10 A0~{-WS}-I/O (io), B11 D0-DIN-I/O (io), C1 I/O (io), C2 TCLKIN-I/O (io), C5 A7-I/O (io), C6 GND (power), C7 A5-I/O (io), C10 DOUT-I/O (io), C11 RDY~{/BUSY}-~{RCLK}-I/O (io), D1 I/O (io), D2 I/O (io), D10 D1-I/O (io), D11 NC, E1 I/O (io), E2 I/O (io), E3 I/O (io), E9 I/O (io), E10 D2-I/O (io), E11 ~{CS}1-I/O (io), F1 I/O (io), F2 I/O (io), F3 VCC (power), F9 VCC (power), F10 D5-I/O (io), F11 D3-I/O (io), G1 I/O (io), G2 I/O (io), G3 I/O (io), G9 I/O (io), G10 ~{CS}0-I/O (io), G11 D4-I/O (io), H1 I/O (io), H2 I/O (io), H10 D6-I/O (io), H11 I/O (io), J1 I/O (io), J2 M1~{-RDATA} (out), J5 I/O (io), J6 GND (power), J7 I/O (io), J10 DONE-~{PROG} (out), J11 XTL1(OUT)-BLKIN-I/O (io), K1 I/O (io), K2 M2-I/O (io), K3 HDC-I/O (io), K4 I/O (io), K5 I/O (io), K6 ~{INIT}-I/O (io), K7 I/O (io), K8 I/O (io), K9 I/O (io), K10 ~{RESET} (in), K11 D7-I/O (io), L1 M0-RTRIG (in), L2 I/O (io), L3 ~{LDC}-I/O (io), L4 NC, L5 NC, L6 I/O (io), L7 I/O (io), L8 I/O (io), L9 NC, L10 NC, L11 XTL2(IN) -I/O (io)

## XC3120A-5PG84I
designator U?
Logic Cell Array with 64 CLBs, with 64 I/O Pins, 84-Pin PGA, Industrial Grade; ComponentAvailability: Not for New Design
footprint PG84 (PGA, 85-Leads, Body 28x28mm, Pitch 2.54mm)
3D model XC3120A-PG84 (84-Pin Ceramic Pin Grid Array (PG84))
pins: A1 A9-I/O (io), A2 A8-I/O (io), A3 A11-I/O (io), A4 NC, A5 A6-I/O (io), A6 A13-I/O (io), A7 A14-I/O (io), A8 NC, A9 A3-I/O (io), A10 A2-I/O (io), A11 CCLK (io), B1 NC, B2 ~{PWRDN} (in), B3 A10-I/O (io), B4 NC, B5 A12-I/O (io), B6 A15-I/O (io), B7 A4-I/O (io), B8 NC, B9 A1-CS2-I/O (io), B10 A0~{-WS}-I/O (io), B11 D0-DIN-I/O (io), C1 I/O (io), C2 TCLKIN-I/O (io), C5 A7-I/O (io), C6 GND (power), C7 A5-I/O (io), C10 DOUT-I/O (io), C11 RDY~{/BUSY}-~{RCLK}-I/O (io), D1 I/O (io), D2 I/O (io), D10 D1-I/O (io), D11 NC, E1 I/O (io), E2 I/O (io), E3 I/O (io), E9 I/O (io), E10 D2-I/O (io), E11 ~{CS}1-I/O (io), F1 I/O (io), F2 I/O (io), F3 VCC (power), F9 VCC (power), F10 D5-I/O (io), F11 D3-I/O (io), G1 I/O (io), G2 I/O (io), G3 I/O (io), G9 I/O (io), G10 ~{CS}0-I/O (io), G11 D4-I/O (io), H1 I/O (io), H2 I/O (io), H10 D6-I/O (io), H11 I/O (io), J1 I/O (io), J2 M1~{-RDATA} (out), J5 I/O (io), J6 GND (power), J7 I/O (io), J10 DONE-~{PROG} (out), J11 XTL1(OUT)-BLKIN-I/O (io), K1 I/O (io), K2 M2-I/O (io), K3 HDC-I/O (io), K4 I/O (io), K5 I/O (io), K6 ~{INIT}-I/O (io), K7 I/O (io), K8 I/O (io), K9 I/O (io), K10 ~{RESET} (in), K11 D7-I/O (io), L1 M0-RTRIG (in), L2 I/O (io), L3 ~{LDC}-I/O (io), L4 NC, L5 NC, L6 I/O (io), L7 I/O (io), L8 I/O (io), L9 NC, L10 NC, L11 XTL2(IN) -I/O (io)

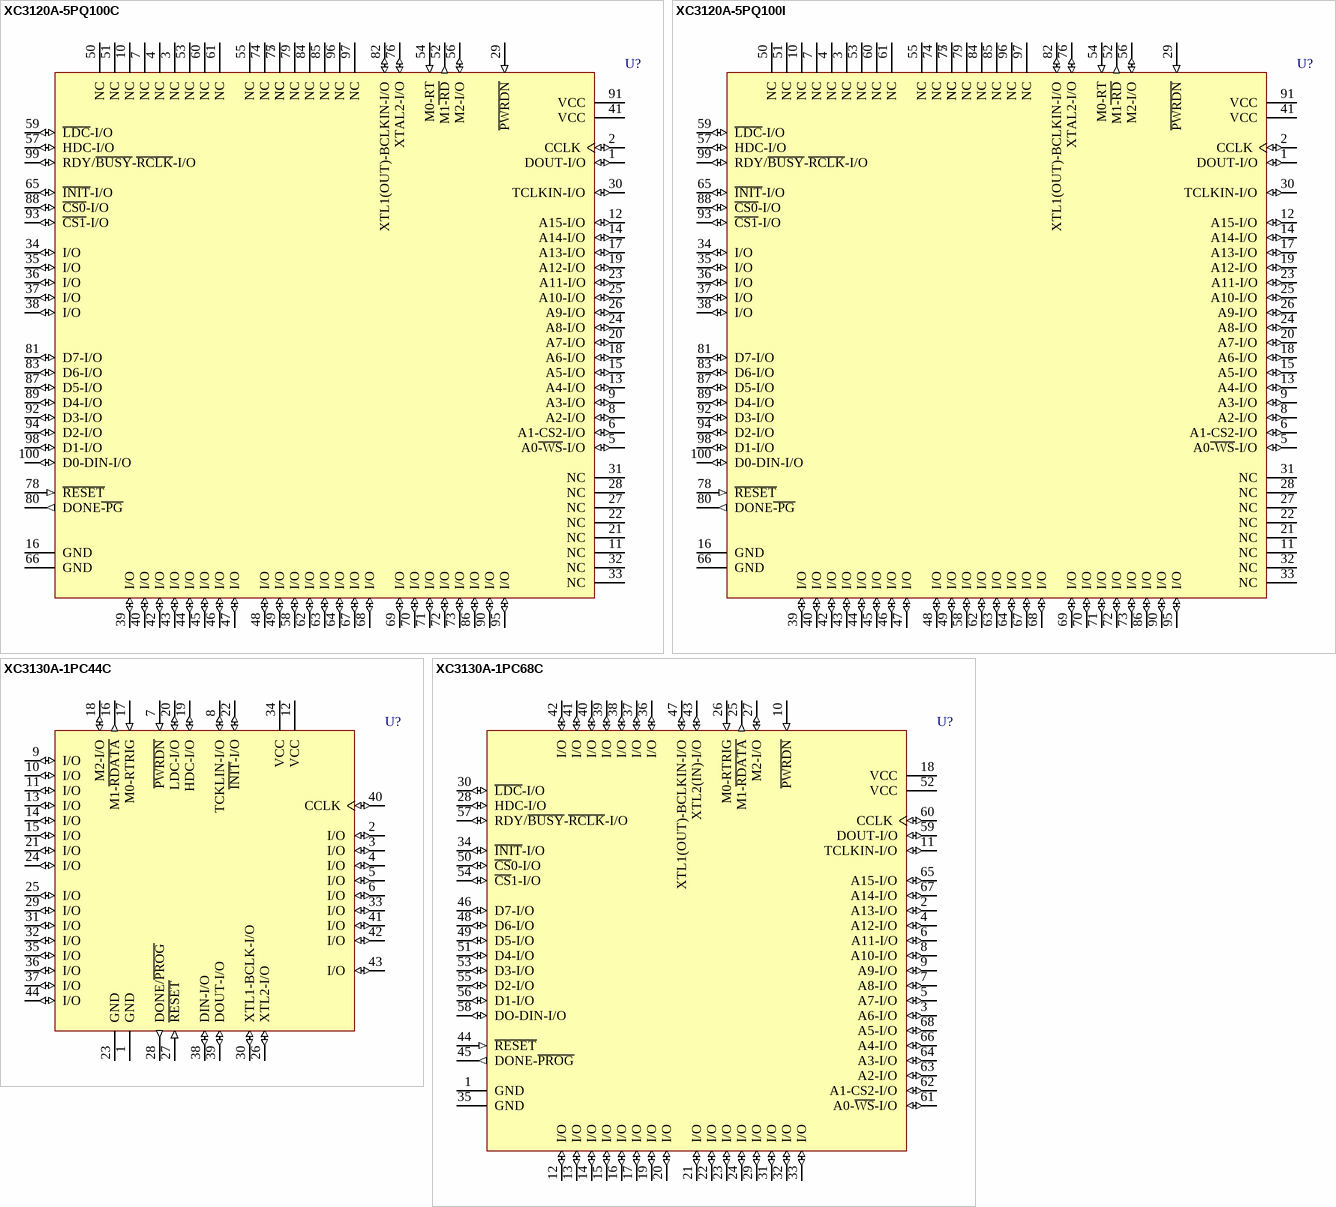
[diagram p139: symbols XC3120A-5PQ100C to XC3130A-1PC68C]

## XC3120A-5PQ100C
designator U?
Logic Cell Array with 64 CLBs, with 64 I/O Pins, 100-Pin PQFP, Commercial Grade; ComponentAvailability: Not for New Design
footprint PQ100_N (QFP, 100-Leads, Body 20x14mm, Pitch 0.65mm, IPC Medium Density)
footprint PQ100_L (QFP, 100-Leads, Body 20x14mm, Pitch 0.65mm, IPC High Density)
footprint PQ100_M (QFP, 100-Leads, Body 20x14mm, Pitch 0.65mm, IPC Low Density)
3D model XC3120A-PQ100 (100-Pin Plastic Quad Flat Pack (PQ100))
pins: 1 DOUT-I/O (io), 2 CCLK (io), 3 NC, 4 NC, 5 A0~{-WS}-I/O (io), 6 A1-CS2-I/O (io), 7 NC, 8 A2-I/O (io), 9 A3-I/O (io), 10 NC, 11 NC, 12 A15-I/O (io), 13 A4-I/O (io), 14 A14-I/O (io), 15 A5-I/O (io), 16 GND (power), 17 A13-I/O (io), 18 A6-I/O (io), 19 A12-I/O (io), 20 A7-I/O (io), 21 NC, 22 NC, 23 A11-I/O (io), 24 A8-I/O (io), 25 A10-I/O (io), 26 A9-I/O (io), 27 NC, 28 NC, 29 ~{PWRDN} (in), 30 TCLKIN-I/O (io), 31 NC, 32 NC, 33 NC, 34 I/O (io), 35 I/O (io), 36 I/O (io), 37 I/O (io), 38 I/O (io), 39 I/O (io), 40 I/O (io), 41 VCC (power), 42 I/O (io), 43 I/O (io), 44 I/O (io), 45 I/O (io), 46 I/O (io), 47 I/O (io), 48 I/O (io), 49 I/O (io), 50 NC, 51 NC, 52 M1~{-RD} (out), 53 NC, 54 M0-RT (in), 55 NC, 56 M2-I/O (io), 57 HDC-I/O (io), 58 I/O (io), 59 ~{LDC}-I/O (io), 60 NC, 61 NC, 62 I/O (io), 63 I/O (io), 64 I/O (io), 65 ~{INIT}-I/O (io), 66 GND (power), 67 I/O (io), 68 I/O (io), 69 I/O (io), 70 I/O (io), 71 I/O (io), 72 I/O (io), 73 I/O (io), 74 NC, 75 NC, 76 XTAL2-I/O (io), 77 NC, 78 ~{RESET} (in), 79 NC, 80 DONE~{-PG} (out), 81 D7-I/O (io), 82 XTL1(OUT)-BCLKIN-I/O (io), 83 D6-I/O (io), 84 NC, 85 NC, 86 I/O (io), 87 D5-I/O (io), 88 ~{CS0}-I/O (io), 89 D4-I/O (io), 90 I/O (io), 91 VCC (power), 92 D3-I/O (io), 93 ~{CS1}-I/O (io), 94 D2-I/O (io), 95 I/O (io), 96 NC, 97 NC, 98 D1-I/O (io), 99 RDY/~{BUSY}-~{RCLK}-I/O (io), 100 D0-DIN-I/O (io)

## XC3120A-5PQ100I
designator U?
Logic Cell Array with 64 CLBs, with 64 I/O Pins, 100-Pin PQFP, Industrial Grade; ComponentAvailability: Not for New Design
footprint PQ100_N (QFP, 100-Leads, Body 20x14mm, Pitch 0.65mm, IPC Medium Density)
footprint PQ100_L (QFP, 100-Leads, Body 20x14mm, Pitch 0.65mm, IPC High Density)
footprint PQ100_M (QFP, 100-Leads, Body 20x14mm, Pitch 0.65mm, IPC Low Density)
3D model XC3120A-PQ100 (100-Pin Plastic Quad Flat Pack (PQ100))
pins: 1 DOUT-I/O (io), 2 CCLK (io), 3 NC, 4 NC, 5 A0~{-WS}-I/O (io), 6 A1-CS2-I/O (io), 7 NC, 8 A2-I/O (io), 9 A3-I/O (io), 10 NC, 11 NC, 12 A15-I/O (io), 13 A4-I/O (io), 14 A14-I/O (io), 15 A5-I/O (io), 16 GND (power), 17 A13-I/O (io), 18 A6-I/O (io), 19 A12-I/O (io), 20 A7-I/O (io), 21 NC, 22 NC, 23 A11-I/O (io), 24 A8-I/O (io), 25 A10-I/O (io), 26 A9-I/O (io), 27 NC, 28 NC, 29 ~{PWRDN} (in), 30 TCLKIN-I/O (io), 31 NC, 32 NC, 33 NC, 34 I/O (io), 35 I/O (io), 36 I/O (io), 37 I/O (io), 38 I/O (io), 39 I/O (io), 40 I/O (io), 41 VCC (power), 42 I/O (io), 43 I/O (io), 44 I/O (io), 45 I/O (io), 46 I/O (io), 47 I/O (io), 48 I/O (io), 49 I/O (io), 50 NC, 51 NC, 52 M1~{-RD} (out), 53 NC, 54 M0-RT (in), 55 NC, 56 M2-I/O (io), 57 HDC-I/O (io), 58 I/O (io), 59 ~{LDC}-I/O (io), 60 NC, 61 NC, 62 I/O (io), 63 I/O (io), 64 I/O (io), 65 ~{INIT}-I/O (io), 66 GND (power), 67 I/O (io), 68 I/O (io), 69 I/O (io), 70 I/O (io), 71 I/O (io), 72 I/O (io), 73 I/O (io), 74 NC, 75 NC, 76 XTAL2-I/O (io), 77 NC, 78 ~{RESET} (in), 79 NC, 80 DONE~{-PG} (out), 81 D7-I/O (io), 82 XTL1(OUT)-BCLKIN-I/O (io), 83 D6-I/O (io), 84 NC, 85 NC, 86 I/O (io), 87 D5-I/O (io), 88 ~{CS0}-I/O (io), 89 D4-I/O (io), 90 I/O (io), 91 VCC (power), 92 D3-I/O (io), 93 ~{CS1}-I/O (io), 94 D2-I/O (io), 95 I/O (io), 96 NC, 97 NC, 98 D1-I/O (io), 99 RDY/~{BUSY}-~{RCLK}-I/O (io), 100 D0-DIN-I/O (io)

## XC3130A-1PC44C
designator U?
Logic Cell Array with 100 CLBs, with 34 I/O Pins, 44-Pin PLCC, Commercial Grade; ComponentAvailability: Not for New Design
footprint PC44_N (Leaded Chip Carrier, 44-Leads, Body 16.6x16.6mm, Pitch 1.27mm, IPC Medium Density)
footprint PC44_L (Leaded Chip Carrier, 44-Leads, Body 16.6x16.6mm, Pitch 1.27mm, IPC High Density)
footprint PC44_M (Leaded Chip Carrier, 44-Leads, Body 16.6x16.6mm, Pitch 1.27mm, IPC Low Density)
3D model XC3130A-PC44 (44-Pin Plastic Leaded Chip Carrier (PC44))
pins: 1 GND (power), 2 I/O (io), 3 I/O (io), 4 I/O (io), 5 I/O (io), 6 I/O (io), 7 ~{PWRDN} (in), 8 TCKLIN-I/O (io), 9 I/O (io), 10 I/O (io), 11 I/O (io), 12 VCC (power), 13 I/O (io), 14 I/O (io), 15 I/O (io), 16 M1-~{RDATA} (out), 17 M0-RTRIG (in), 18 M2-I/O (io), 19 HDC-I/O (io), 20 LDC-I/O (io), 21 I/O (io), 22 ~{INIT}-I/O (io), 23 GND (power), 24 I/O (io), 25 I/O (io), 26 XTL2-I/O (io), 27 ~{RESET} (in), 28 DONE/~{PROG} (out), 29 I/O (io), 30 XTL1-BCLK-I/O (io), 31 I/O (io), 32 I/O (io), 33 I/O (io), 34 VCC (power), 35 I/O (io), 36 I/O (io), 37 I/O (io), 38 DIN-I/O (io), 39 DOUT-I/O (io), 40 CCLK (io), 41 I/O (io), 42 I/O (io), 43 I/O (io), 44 I/O (io)

## XC3130A-1PC68C
designator U?
Logic Cell Array with 100 CLBs, with 58 I/O Pins, 68-Pin PLCC, Commercial Grade; ComponentAvailability: Not for New Design
footprint PC68_N (Leaded Chip Carrier, 68-Leads, Body 24x24mm, Pitch 1.27mm, IPC Medium Density)
footprint PC68_L (Leaded Chip Carrier, 68-Leads, Body 24x24mm, Pitch 1.27mm, IPC High Density)
footprint PC68_M (Leaded Chip Carrier, 68-Leads, Body 24x24mm, Pitch 1.27mm, IPC Low Density)
3D model XC3130A-PC68 (68-Pin Plastic Leaded Chip Carrier (PC68))
pins: 1 GND (power), 2 A13-I/O (io), 3 A6-I/O (io), 4 A12-I/O (io), 5 A7-I/O (io), 6 A11-I/O (io), 7 A8-I/O (io), 8 A10-I/O (io), 9 A9-I/O (io), 10 ~{PWRDN} (in), 11 TCLKIN-I/O (io), 12 I/O (io), 13 I/O (io), 14 I/O (io), 15 I/O (io), 16 I/O (io), 17 I/O (io), 18 VCC (power), 19 I/O (io), 20 I/O (io), 21 I/O (io), 22 I/O (io), 23 I/O (io), 24 I/O (io), 25 M1-~{RDATA} (out), 26 M0-RTRIG (in), 27 M2-I/O (io), 28 HDC-I/O (io), 29 I/O (io), 30 ~{LDC}-I/O (io), 31 I/O (io), 32 I/O (io), 33 I/O (io), 34 ~{INIT}-I/O (io), 35 GND (power), 36 I/O (io), 37 I/O (io), 38 I/O (io), 39 I/O (io), 40 I/O (io), 41 I/O (io), 42 I/O (io), 43 XTL2(IN)-I/O (io), 44 ~{RESET} (in), 45 DONE-~{PROG} (out), 46 D7-I/O (io), 47 XTL1(OUT)-BCLKIN-I/O (io), 48 D6-I/O (io), 49 D5-I/O (io), 50 ~{CS}0-I/O (io), 51 D4-I/O (io), 52 VCC (power), 53 D3-I/O (io), 54 ~{CS}1-I/O (io), 55 D2-I/O (io), 56 D1-I/O (io), 57 RDY/~{BUSY}-~{RCLK}-I/O (io), 58 DO-DIN-I/O (io), 59 DOUT-I/O (io), 60 CCLK (io), 61 A0-~{WS}-I/O (io), 62 A1-CS2-I/O (io), 63 A2-I/O (io), 64 A3-I/O (io), 65 A15-I/O (io), 66 A4-I/O (io), 67 A14-I/O (io), 68 A5-I/O (io)

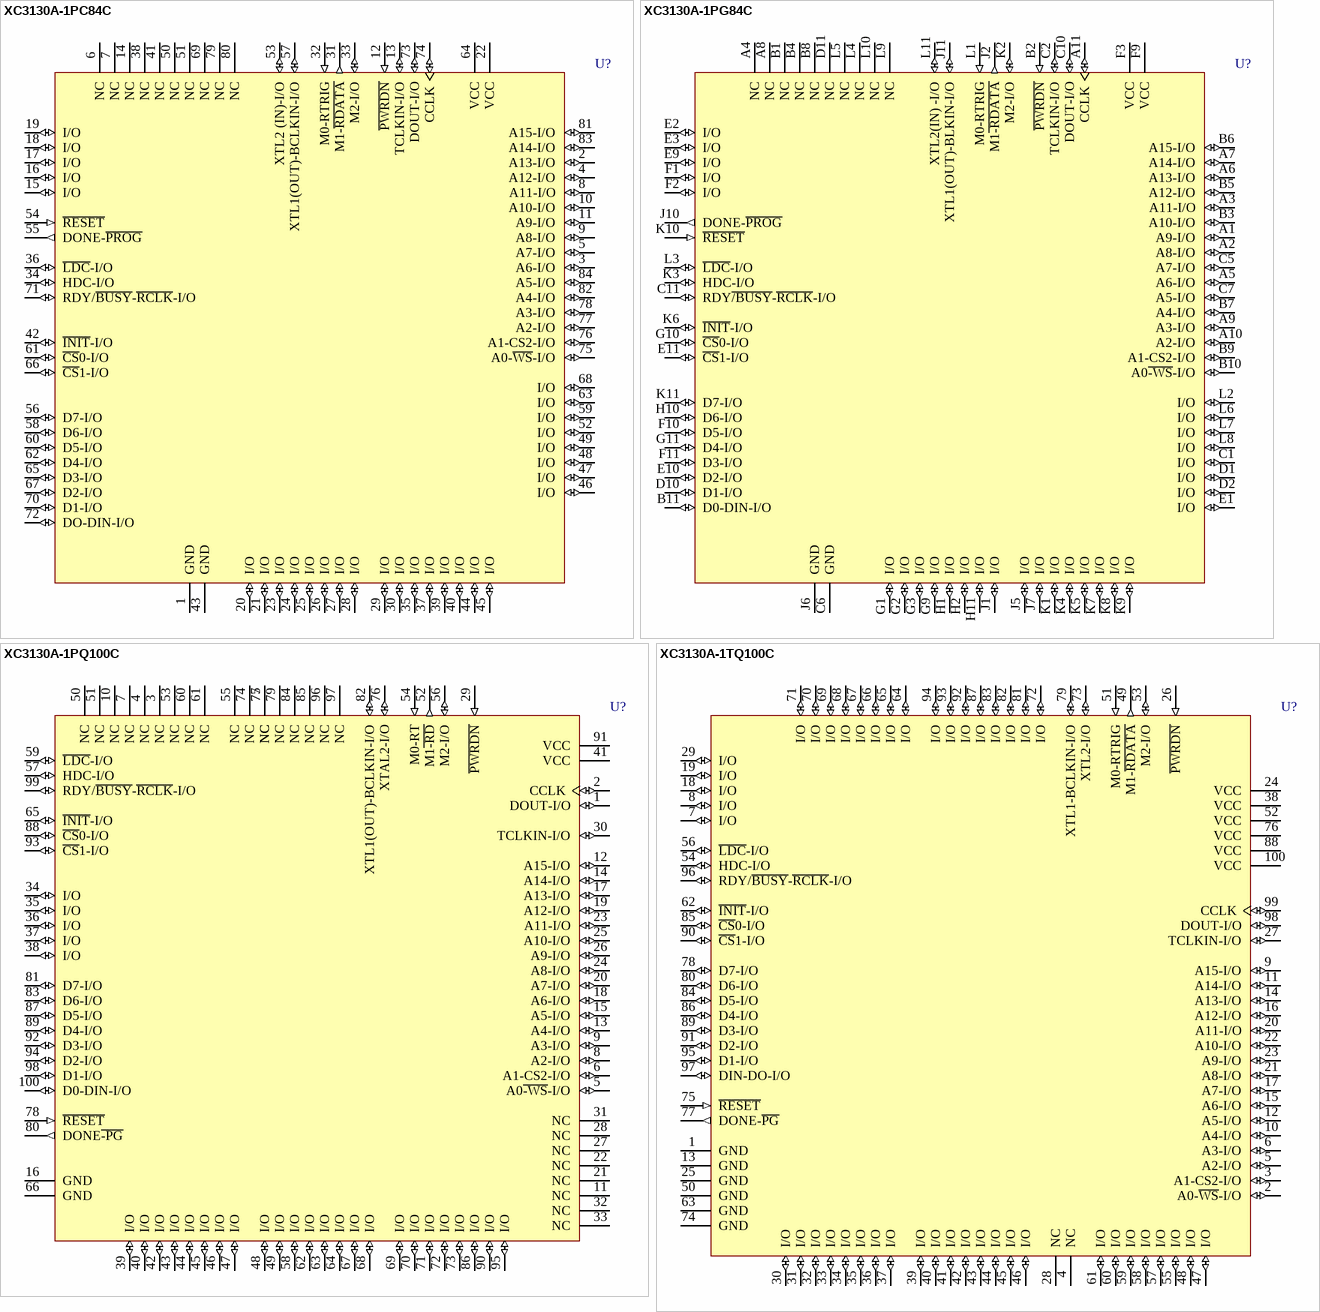
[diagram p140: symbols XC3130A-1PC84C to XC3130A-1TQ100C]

## XC3130A-1PC84C
designator U?
Logic Cell Array with 100 CLBs, with 64 I/O Pins, 84-Pin PLCC, Commercial Grade; ComponentAvailability: Not for New Design
footprint PC84_N (Leaded Chip Carrier, 84-Leads, Body 29.3x29.3mm, Pitch 1.27mm, IPC Medium Density)
footprint PC84_L (Leaded Chip Carrier, 84-Leads, Body 29.3x29.3mm, Pitch 1.27mm, IPC High Density)
footprint PC84_M (Leaded Chip Carrier, 84-Leads, Body 29.3x29.3mm, Pitch 1.27mm, IPC Low Density)
3D model XC3130A-PC84 (84-Pin Plastic Leaded Chip Carrier (PC84))
pins: 1 GND (power), 2 A13-I/O (io), 3 A6-I/O (io), 4 A12-I/O (io), 5 A7-I/O (io), 6 NC, 7 NC, 8 A11-I/O (io), 9 A8-I/O (io), 10 A10-I/O (io), 11 A9-I/O (io), 12 ~{PWRDN} (in), 13 TCLKIN-I/O (io), 14 NC, 15 I/O (io), 16 I/O (io), 17 I/O (io), 18 I/O (io), 19 I/O (io), 20 I/O (io), 21 I/O (io), 22 VCC (power), 23 I/O (io), 24 I/O (io), 25 I/O (io), 26 I/O (io), 27 I/O (io), 28 I/O (io), 29 I/O (io), 30 I/O (io), 31 M1-~{RDATA} (out), 32 M0-RTRIG (in), 33 M2-I/O (io), 34 HDC-I/O (io), 35 I/O (io), 36 ~{LDC}-I/O (io), 37 I/O (io), 38 NC, 39 I/O (io), 40 I/O (io), 41 NC, 42 ~{INIT}-I/O (io), 43 GND (power), 44 I/O (io), 45 I/O (io), 46 I/O (io), 47 I/O (io), 48 I/O (io), 49 I/O (io), 50 NC, 51 NC, 52 I/O (io), 53 XTL2 (IN)-I/O (io), 54 ~{RESET} (in), 55 DONE-~{PROG} (out), 56 D7-I/O (io), 57 XTL1(OUT)-BCLKIN-I/O (io), 58 D6-I/O (io), 59 I/O (io), 60 D5-I/O (io), 61 ~{CS}0-I/O (io), 62 D4-I/O (io), 63 I/O (io), 64 VCC (power), 65 D3-I/O (io), 66 ~{CS}1-I/O (io), 67 D2-I/O (io), 68 I/O (io), 69 NC, 70 D1-I/O (io), 71 RDY/~{BUSY}-~{RCLK}-I/O (io), 72 DO-DIN-I/O (io), 73 DOUT-I/O (io), 74 CCLK (io), 75 A0-~{WS}-I/O (io), 76 A1-CS2-I/O (io), 77 A2-I/O (io), 78 A3-I/O (io), 79 NC, 80 NC, 81 A15-I/O (io), 82 A4-I/O (io), 83 A14-I/O (io), 84 A5-I/O (io)

## XC3130A-1PG84C
designator U?
Logic Cell Array with 100 CLBs, with 64 I/O Pins, 84-Pin PGA, Commercial Grade; ComponentAvailability: Not for New Design
footprint PG84 (PGA, 85-Leads, Body 28x28mm, Pitch 2.54mm)
3D model XC3130A-PG84 (84-Pin Ceramic Pin Grid Array (PG84))
pins: A1 A9-I/O (io), A2 A8-I/O (io), A3 A11-I/O (io), A4 NC, A5 A6-I/O (io), A6 A13-I/O (io), A7 A14-I/O (io), A8 NC, A9 A3-I/O (io), A10 A2-I/O (io), A11 CCLK (io), B1 NC, B2 ~{PWRDN} (in), B3 A10-I/O (io), B4 NC, B5 A12-I/O (io), B6 A15-I/O (io), B7 A4-I/O (io), B8 NC, B9 A1-CS2-I/O (io), B10 A0~{-WS}-I/O (io), B11 D0-DIN-I/O (io), C1 I/O (io), C2 TCLKIN-I/O (io), C5 A7-I/O (io), C6 GND (power), C7 A5-I/O (io), C10 DOUT-I/O (io), C11 RDY~{/BUSY}-~{RCLK}-I/O (io), D1 I/O (io), D2 I/O (io), D10 D1-I/O (io), D11 NC, E1 I/O (io), E2 I/O (io), E3 I/O (io), E9 I/O (io), E10 D2-I/O (io), E11 ~{CS}1-I/O (io), F1 I/O (io), F2 I/O (io), F3 VCC (power), F9 VCC (power), F10 D5-I/O (io), F11 D3-I/O (io), G1 I/O (io), G2 I/O (io), G3 I/O (io), G9 I/O (io), G10 ~{CS}0-I/O (io), G11 D4-I/O (io), H1 I/O (io), H2 I/O (io), H10 D6-I/O (io), H11 I/O (io), J1 I/O (io), J2 M1~{-RDATA} (out), J5 I/O (io), J6 GND (power), J7 I/O (io), J10 DONE-~{PROG} (out), J11 XTL1(OUT)-BLKIN-I/O (io), K1 I/O (io), K2 M2-I/O (io), K3 HDC-I/O (io), K4 I/O (io), K5 I/O (io), K6 ~{INIT}-I/O (io), K7 I/O (io), K8 I/O (io), K9 I/O (io), K10 ~{RESET} (in), K11 D7-I/O (io), L1 M0-RTRIG (in), L2 I/O (io), L3 ~{LDC}-I/O (io), L4 NC, L5 NC, L6 I/O (io), L7 I/O (io), L8 I/O (io), L9 NC, L10 NC, L11 XTL2(IN) -I/O (io)

## XC3130A-1PQ100C
designator U?
Logic Cell Array with 100 CLBs, with 64 I/O Pins, 100-Pin PQFP, Commercial Grade; ComponentAvailability: Not for New Design
footprint PQ100_N (QFP, 100-Leads, Body 20x14mm, Pitch 0.65mm, IPC Medium Density)
footprint PQ100_L (QFP, 100-Leads, Body 20x14mm, Pitch 0.65mm, IPC High Density)
footprint PQ100_M (QFP, 100-Leads, Body 20x14mm, Pitch 0.65mm, IPC Low Density)
3D model XC3130A-PQ100 (100-Pin Plastic Quad Flat Pack (PQ100))
pins: 1 DOUT-I/O (io), 2 CCLK (io), 3 NC, 4 NC, 5 A0~{-WS}-I/O (io), 6 A1-CS2-I/O (io), 7 NC, 8 A2-I/O (io), 9 A3-I/O (io), 10 NC, 11 NC, 12 A15-I/O (io), 13 A4-I/O (io), 14 A14-I/O (io), 15 A5-I/O (io), 16 GND (power), 17 A13-I/O (io), 18 A6-I/O (io), 19 A12-I/O (io), 20 A7-I/O (io), 21 NC, 22 NC, 23 A11-I/O (io), 24 A8-I/O (io), 25 A10-I/O (io), 26 A9-I/O (io), 27 NC, 28 NC, 29 ~{PWRDN} (in), 30 TCLKIN-I/O (io), 31 NC, 32 NC, 33 NC, 34 I/O (io), 35 I/O (io), 36 I/O (io), 37 I/O (io), 38 I/O (io), 39 I/O (io), 40 I/O (io), 41 VCC (power), 42 I/O (io), 43 I/O (io), 44 I/O (io), 45 I/O (io), 46 I/O (io), 47 I/O (io), 48 I/O (io), 49 I/O (io), 50 NC, 51 NC, 52 M1~{-RD} (out), 53 NC, 54 M0-RT (in), 55 NC, 56 M2-I/O (io), 57 HDC-I/O (io), 58 I/O (io), 59 ~{LDC}-I/O (io), 60 NC, 61 NC, 62 I/O (io), 63 I/O (io), 64 I/O (io), 65 ~{INIT}-I/O (io), 66 GND (power), 67 I/O (io), 68 I/O (io), 69 I/O (io), 70 I/O (io), 71 I/O (io), 72 I/O (io), 73 I/O (io), 74 NC, 75 NC, 76 XTAL2-I/O (io), 77 NC, 78 ~{RESET} (in), 79 NC, 80 DONE~{-PG} (out), 81 D7-I/O (io), 82 XTL1(OUT)-BCLKIN-I/O (io), 83 D6-I/O (io), 84 NC, 85 NC, 86 I/O (io), 87 D5-I/O (io), 88 ~{CS}0-I/O (io), 89 D4-I/O (io), 90 I/O (io), 91 VCC (power), 92 D3-I/O (io), 93 ~{CS}1-I/O (io), 94 D2-I/O (io), 95 I/O (io), 96 NC, 97 NC, 98 D1-I/O (io), 99 RDY/~{BUSY}-~{RCLK}-I/O (io), 100 D0-DIN-I/O (io)

## XC3130A-1TQ100C
designator U?
Logic Cell Array with 100 CLBs, with 80 I/O Pins, 100-Pin TQFP, Commercial Grade; ComponentAvailability: Not for New Design
footprint TQ100_N (Thin QFP, 100-Leads, Body 14x14mm, Pitch 0.5mm, IPC Medium Density)
footprint TQ100_L (Thin QFP, 100-Leads, Body 14x14mm, Pitch 0.5mm, IPC High Density)
footprint TQ100_M (Thin QFP, 100-Leads, Body 14x14mm, Pitch 0.5mm, IPC Low Density)
3D model XC3130A-TQ100 (100-Pin Thin Quad Flat Pack (TQ100))
pins: 1 GND (power), 2 A0-~{WS}-I/O (io), 3 A1-CS2-I/O (io), 4 NC, 5 A2-I/O (io), 6 A3-I/O (io), 7 I/O (io), 8 I/O (io), 9 A15-I/O (io), 10 A4-I/O (io), 11 A14-I/O (io), 12 A5-I/O (io), 13 GND (power), 14 A13-I/O (io), 15 A6-I/O (io), 16 A12-I/O (io), 17 A7-I/O (io), 18 I/O (io), 19 I/O (io), 20 A11-I/O (io), 21 A8-I/O (io), 22 A10-I/O (io), 23 A9-I/O (io), 24 VCC (power), 25 GND (power), 26 ~{PWRDN} (in), 27 TCLKIN-I/O (io), 28 NC, 29 I/O (io), 30 I/O (io), 31 I/O (io), 32 I/O (io), 33 I/O (io), 34 I/O (io), 35 I/O (io), 36 I/O (io), 37 I/O (io), 38 VCC (power), 39 I/O (io), 40 I/O (io), 41 I/O (io), 42 I/O (io), 43 I/O (io), 44 I/O (io), 45 I/O (io), 46 I/O (io), 47 I/O (io), 48 I/O (io), 49 M1-~{RDATA} (out), 50 GND (power), 51 M0-RTRIG (in), 52 VCC (power), 53 M2-I/O (io), 54 HDC-I/O (io), 55 I/O (io), 56 ~{LDC}-I/O (io), 57 I/O (io), 58 I/O (io), 59 I/O (io), 60 I/O (io), 61 I/O (io), 62 ~{INIT}-I/O (io), 63 GND (power), 64 I/O (io), 65 I/O (io), 66 I/O (io), 67 I/O (io), 68 I/O (io), 69 I/O (io), 70 I/O (io), 71 I/O (io), 72 I/O (io), 73 XTL2-I/O (io), 74 GND (power), 75 ~{RESET} (in), 76 VCC (power), 77 DONE-~{PG} (out), 78 D7-I/O (io), 79 XTL1-BCLKIN-I/O (io), 80 D6-I/O (io), 81 I/O (io), 82 I/O (io), 83 I/O (io), 84 D5-I/O (io), 85 ~{CS}0-I/O (io), 86 D4-I/O (io), 87 I/O (io), 88 VCC (power), 89 D3-I/O (io), 90 ~{CS}1-I/O (io), 91 D2-I/O (io), 92 I/O (io), 93 I/O (io), 94 I/O (io), 95 D1-I/O (io), 96 RDY/~{BUSY}-~{RCLK}-I/O (io), 97 DIN-DO-I/O (io), 98 DOUT-I/O (io), 99 CCLK (io), 100 VCC (power)

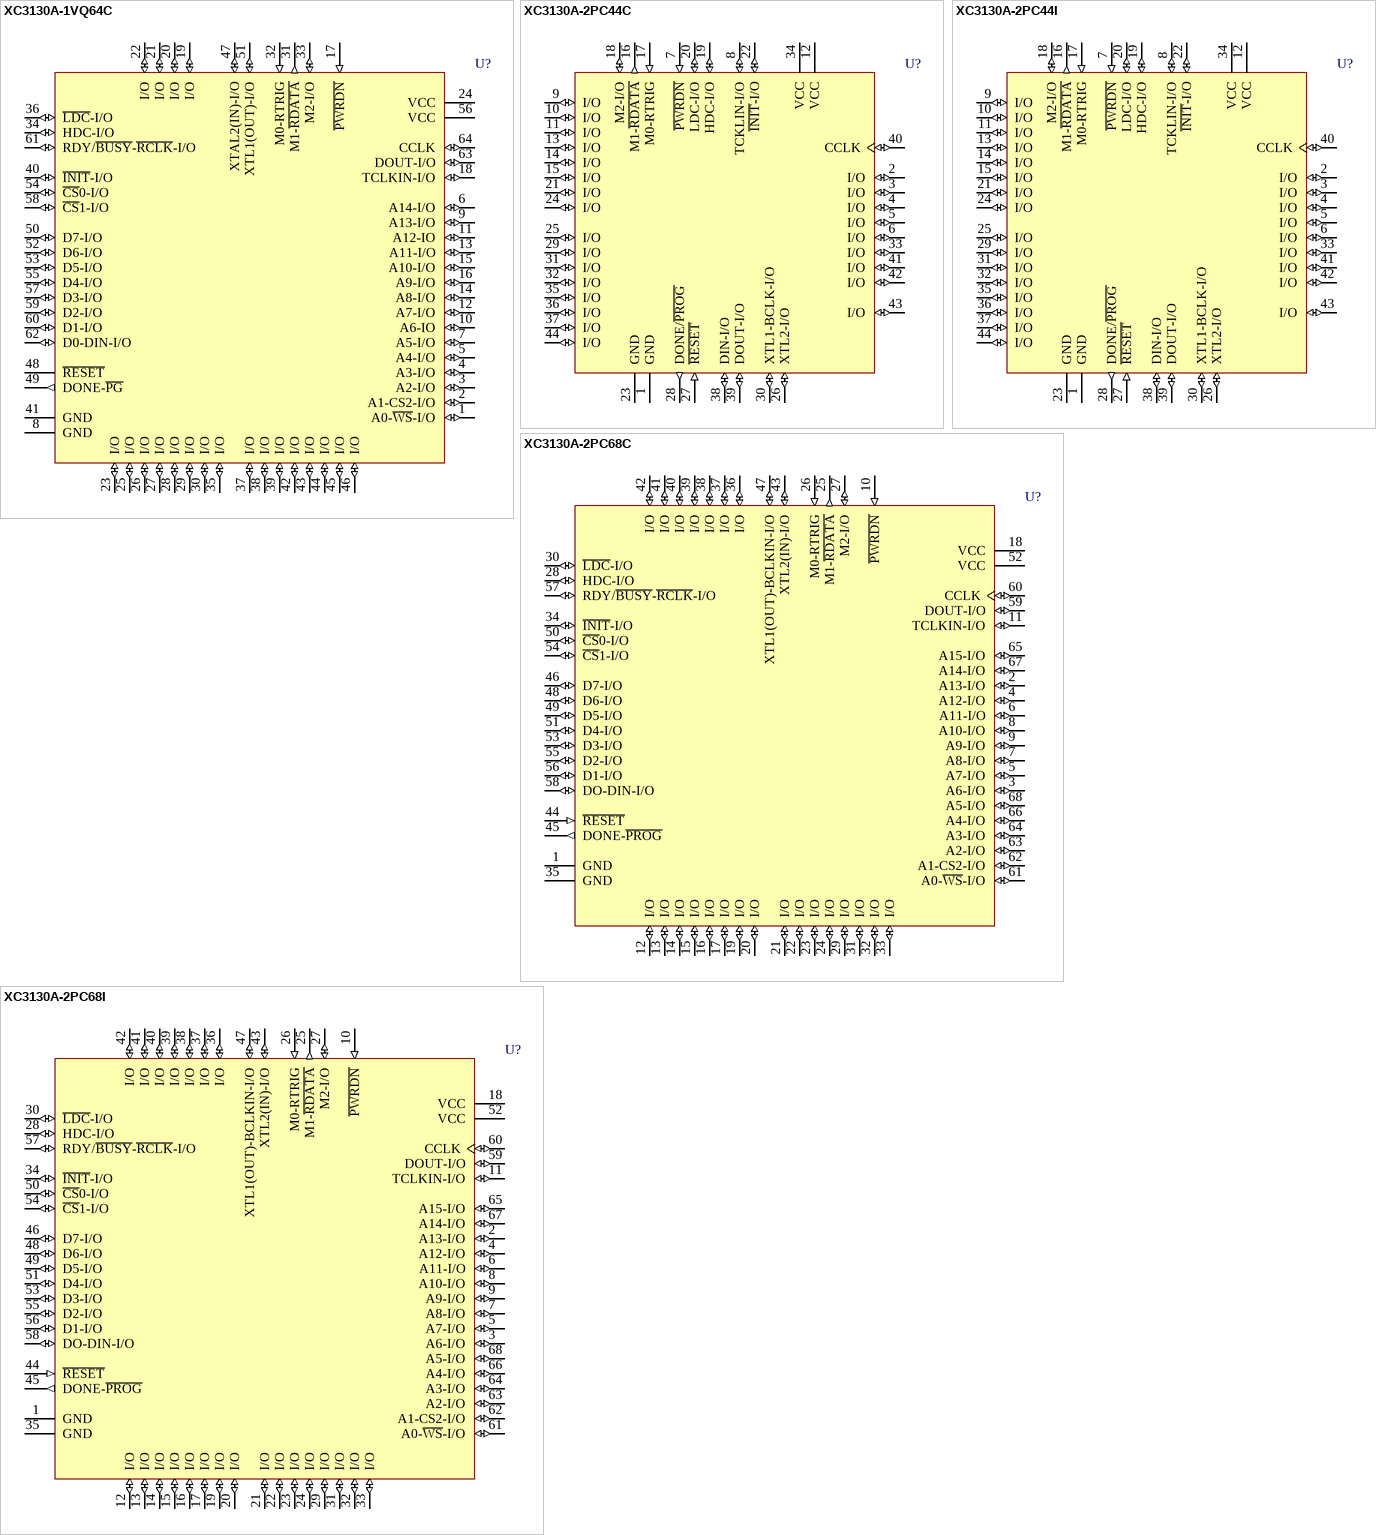
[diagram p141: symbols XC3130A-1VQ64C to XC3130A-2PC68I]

## XC3130A-1VQ64C
designator U?
Logic Cell Array with 100 CLBs, with 52 I/O Pins, 64-Pin VQFP, Commercial Grade; ComponentAvailability: Not for New Design
footprint VQ64_N (Thin QFP, 64-Leads, Body 10x10mm, Pitch 0.5mm, IPC Medium Density)
footprint VQ64_L (Thin QFP, 64-Leads, Body 10x10mm, Pitch 0.5mm, IPC High Density)
footprint VQ64_M (Thin QFP, 64-Leads, Body 10x10mm, Pitch 0.5mm, IPC Low Density)
3D model XC3130A-VQ64 (64-Pin Very Thin Quad Flat Pack (VQ64))
pins: 1 A0-~{WS}-I/O (io), 2 A1-CS2-I/O (io), 3 A2-I/O (io), 4 A3-I/O (io), 5 A4-I/O (io), 6 A14-I/O (io), 7 A5-I/O (io), 8 GND (power), 9 A13-I/O (io), 10 A6-IO (io), 11 A12-IO (io), 12 A7-I/O (io), 13 A11-I/O (io), 14 A8-I/O (io), 15 A10-I/O (io), 16 A9-I/O (io), 17 ~{PWRDN} (in), 18 TCLKIN-I/O (io), 19 I/O (io), 20 I/O (io), 21 I/O (io), 22 I/O (io), 23 I/O (io), 24 VCC (power), 25 I/O (io), 26 I/O (io), 27 I/O (io), 28 I/O (io), 29 I/O (io), 30 I/O (io), 31 M1-~{RDATA} (out), 32 M0-RTRIG (in), 33 M2-I/O (io), 34 HDC-I/O (io), 35 I/O (io), 36 ~{LDC}-I/O (io), 37 I/O (io), 38 I/O (io), 39 I/O (io), 40 ~{INIT}-I/O (io), 41 GND (power), 42 I/O (io), 43 I/O (io), 44 I/O (io), 45 I/O (io), 46 I/O (io), 47 XTAL2(IN)-I/O (io), 48 ~{RESET}, 49 DONE-~{PG} (out), 50 D7-I/O (io), 51 XTL1(OUT)-I/O (io), 52 D6-I/O (io), 53 D5-I/O (io), 54 ~{CS}0-I/O (io), 55 D4-I/O (io), 56 VCC (power), 57 D3-I/O (io), 58 ~{CS}1-I/O (io), 59 D2-I/O (io), 60 D1-I/O (io), 61 RDY/~{BUSY}-~{RCLK}-I/O (io), 62 D0-DIN-I/O (io), 63 DOUT-I/O (io), 64 CCLK (io)

## XC3130A-2PC44C
designator U?
Logic Cell Array with 100 CLBs, with 34 I/O Pins, 44-Pin PLCC, Commercial Grade; ComponentAvailability: Not for New Design
footprint PC44_N (Leaded Chip Carrier, 44-Leads, Body 16.6x16.6mm, Pitch 1.27mm, IPC Medium Density)
footprint PC44_L (Leaded Chip Carrier, 44-Leads, Body 16.6x16.6mm, Pitch 1.27mm, IPC High Density)
footprint PC44_M (Leaded Chip Carrier, 44-Leads, Body 16.6x16.6mm, Pitch 1.27mm, IPC Low Density)
3D model XC3130A-PC44 (44-Pin Plastic Leaded Chip Carrier (PC44))
pins: 1 GND (power), 2 I/O (io), 3 I/O (io), 4 I/O (io), 5 I/O (io), 6 I/O (io), 7 ~{PWRDN} (in), 8 TCKLIN-I/O (io), 9 I/O (io), 10 I/O (io), 11 I/O (io), 12 VCC (power), 13 I/O (io), 14 I/O (io), 15 I/O (io), 16 M1-~{RDATA} (out), 17 M0-RTRIG (in), 18 M2-I/O (io), 19 HDC-I/O (io), 20 LDC-I/O (io), 21 I/O (io), 22 ~{INIT}-I/O (io), 23 GND (power), 24 I/O (io), 25 I/O (io), 26 XTL2-I/O (io), 27 ~{RESET} (in), 28 DONE/~{PROG} (out), 29 I/O (io), 30 XTL1-BCLK-I/O (io), 31 I/O (io), 32 I/O (io), 33 I/O (io), 34 VCC (power), 35 I/O (io), 36 I/O (io), 37 I/O (io), 38 DIN-I/O (io), 39 DOUT-I/O (io), 40 CCLK (io), 41 I/O (io), 42 I/O (io), 43 I/O (io), 44 I/O (io)

## XC3130A-2PC44I
designator U?
Logic Cell Array with 100 CLBs, with 34 I/O Pins, 44-Pin PLCC, Industrial Grade; ComponentAvailability: Not for New Design
footprint PC44_N (Leaded Chip Carrier, 44-Leads, Body 16.6x16.6mm, Pitch 1.27mm, IPC Medium Density)
footprint PC44_L (Leaded Chip Carrier, 44-Leads, Body 16.6x16.6mm, Pitch 1.27mm, IPC High Density)
footprint PC44_M (Leaded Chip Carrier, 44-Leads, Body 16.6x16.6mm, Pitch 1.27mm, IPC Low Density)
3D model XC3130A-PC44 (44-Pin Plastic Leaded Chip Carrier (PC44))
pins: 1 GND (power), 2 I/O (io), 3 I/O (io), 4 I/O (io), 5 I/O (io), 6 I/O (io), 7 ~{PWRDN} (in), 8 TCKLIN-I/O (io), 9 I/O (io), 10 I/O (io), 11 I/O (io), 12 VCC (power), 13 I/O (io), 14 I/O (io), 15 I/O (io), 16 M1-~{RDATA} (out), 17 M0-RTRIG (in), 18 M2-I/O (io), 19 HDC-I/O (io), 20 LDC-I/O (io), 21 I/O (io), 22 ~{INIT}-I/O (io), 23 GND (power), 24 I/O (io), 25 I/O (io), 26 XTL2-I/O (io), 27 ~{RESET} (in), 28 DONE/~{PROG} (out), 29 I/O (io), 30 XTL1-BCLK-I/O (io), 31 I/O (io), 32 I/O (io), 33 I/O (io), 34 VCC (power), 35 I/O (io), 36 I/O (io), 37 I/O (io), 38 DIN-I/O (io), 39 DOUT-I/O (io), 40 CCLK (io), 41 I/O (io), 42 I/O (io), 43 I/O (io), 44 I/O (io)

## XC3130A-2PC68C
designator U?
Logic Cell Array with 100 CLBs, with 58 I/O Pins, 68-Pin PLCC, Commercial Grade; ComponentAvailability: Not for New Design
footprint PC68_N (Leaded Chip Carrier, 68-Leads, Body 24x24mm, Pitch 1.27mm, IPC Medium Density)
footprint PC68_L (Leaded Chip Carrier, 68-Leads, Body 24x24mm, Pitch 1.27mm, IPC High Density)
footprint PC68_M (Leaded Chip Carrier, 68-Leads, Body 24x24mm, Pitch 1.27mm, IPC Low Density)
3D model XC3130A-PC68 (68-Pin Plastic Leaded Chip Carrier (PC68))
pins: 1 GND (power), 2 A13-I/O (io), 3 A6-I/O (io), 4 A12-I/O (io), 5 A7-I/O (io), 6 A11-I/O (io), 7 A8-I/O (io), 8 A10-I/O (io), 9 A9-I/O (io), 10 ~{PWRDN} (in), 11 TCLKIN-I/O (io), 12 I/O (io), 13 I/O (io), 14 I/O (io), 15 I/O (io), 16 I/O (io), 17 I/O (io), 18 VCC (power), 19 I/O (io), 20 I/O (io), 21 I/O (io), 22 I/O (io), 23 I/O (io), 24 I/O (io), 25 M1-~{RDATA} (out), 26 M0-RTRIG (in), 27 M2-I/O (io), 28 HDC-I/O (io), 29 I/O (io), 30 ~{LDC}-I/O (io), 31 I/O (io), 32 I/O (io), 33 I/O (io), 34 ~{INIT}-I/O (io), 35 GND (power), 36 I/O (io), 37 I/O (io), 38 I/O (io), 39 I/O (io), 40 I/O (io), 41 I/O (io), 42 I/O (io), 43 XTL2(IN)-I/O (io), 44 ~{RESET} (in), 45 DONE-~{PROG} (out), 46 D7-I/O (io), 47 XTL1(OUT)-BCLKIN-I/O (io), 48 D6-I/O (io), 49 D5-I/O (io), 50 ~{CS}0-I/O (io), 51 D4-I/O (io), 52 VCC (power), 53 D3-I/O (io), 54 ~{CS}1-I/O (io), 55 D2-I/O (io), 56 D1-I/O (io), 57 RDY/~{BUSY}-~{RCLK}-I/O (io), 58 DO-DIN-I/O (io), 59 DOUT-I/O (io), 60 CCLK (io), 61 A0-~{WS}-I/O (io), 62 A1-CS2-I/O (io), 63 A2-I/O (io), 64 A3-I/O (io), 65 A15-I/O (io), 66 A4-I/O (io), 67 A14-I/O (io), 68 A5-I/O (io)

## XC3130A-2PC68I
designator U?
Logic Cell Array with 100 CLBs, with 58 I/O Pins, 68-Pin PLCC, Industrial Grade; ComponentAvailability: Not for New Design
footprint PC68_N (Leaded Chip Carrier, 68-Leads, Body 24x24mm, Pitch 1.27mm, IPC Medium Density)
footprint PC68_L (Leaded Chip Carrier, 68-Leads, Body 24x24mm, Pitch 1.27mm, IPC High Density)
footprint PC68_M (Leaded Chip Carrier, 68-Leads, Body 24x24mm, Pitch 1.27mm, IPC Low Density)
3D model XC3130A-PC68 (68-Pin Plastic Leaded Chip Carrier (PC68))
pins: 1 GND (power), 2 A13-I/O (io), 3 A6-I/O (io), 4 A12-I/O (io), 5 A7-I/O (io), 6 A11-I/O (io), 7 A8-I/O (io), 8 A10-I/O (io), 9 A9-I/O (io), 10 ~{PWRDN} (in), 11 TCLKIN-I/O (io), 12 I/O (io), 13 I/O (io), 14 I/O (io), 15 I/O (io), 16 I/O (io), 17 I/O (io), 18 VCC (power), 19 I/O (io), 20 I/O (io), 21 I/O (io), 22 I/O (io), 23 I/O (io), 24 I/O (io), 25 M1-~{RDATA} (out), 26 M0-RTRIG (in), 27 M2-I/O (io), 28 HDC-I/O (io), 29 I/O (io), 30 ~{LDC}-I/O (io), 31 I/O (io), 32 I/O (io), 33 I/O (io), 34 ~{INIT}-I/O (io), 35 GND (power), 36 I/O (io), 37 I/O (io), 38 I/O (io), 39 I/O (io), 40 I/O (io), 41 I/O (io), 42 I/O (io), 43 XTL2(IN)-I/O (io), 44 ~{RESET} (in), 45 DONE-~{PROG} (out), 46 D7-I/O (io), 47 XTL1(OUT)-BCLKIN-I/O (io), 48 D6-I/O (io), 49 D5-I/O (io), 50 ~{CS}0-I/O (io), 51 D4-I/O (io), 52 VCC (power), 53 D3-I/O (io), 54 ~{CS}1-I/O (io), 55 D2-I/O (io), 56 D1-I/O (io), 57 RDY/~{BUSY}-~{RCLK}-I/O (io), 58 DO-DIN-I/O (io), 59 DOUT-I/O (io), 60 CCLK (io), 61 A0-~{WS}-I/O (io), 62 A1-CS2-I/O (io), 63 A2-I/O (io), 64 A3-I/O (io), 65 A15-I/O (io), 66 A4-I/O (io), 67 A14-I/O (io), 68 A5-I/O (io)

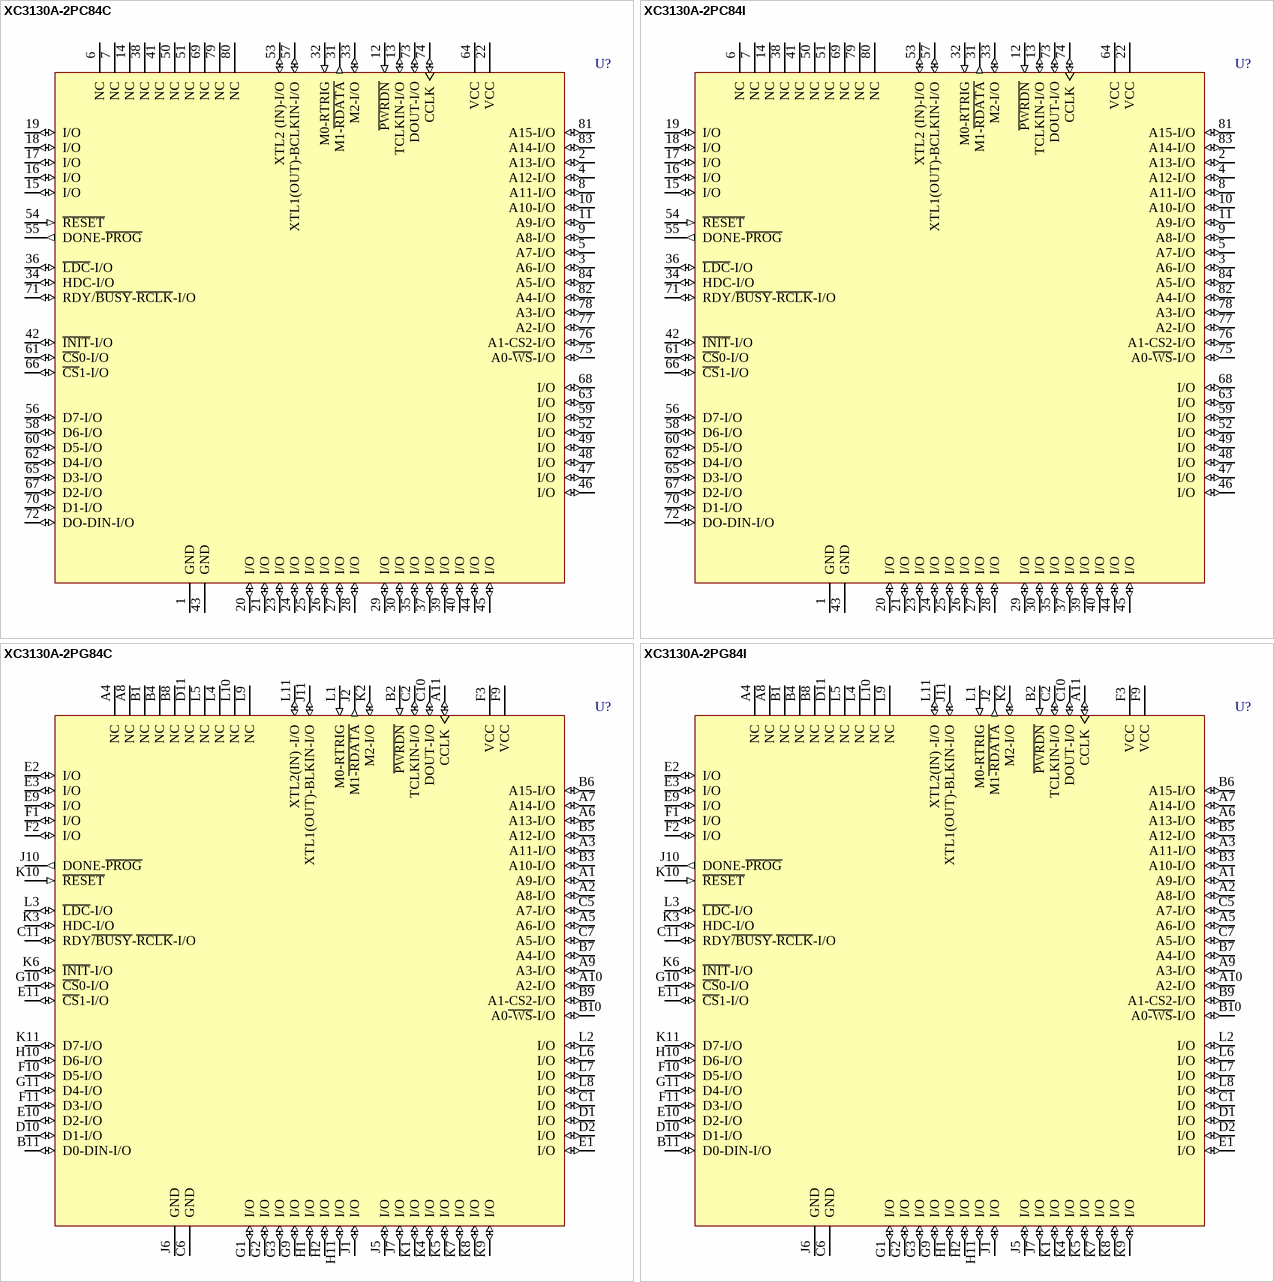
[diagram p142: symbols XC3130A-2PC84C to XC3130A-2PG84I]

## XC3130A-2PC84C
designator U?
Logic Cell Array with 100 CLBs, with 64 I/O Pins, 84-Pin PLCC, Commercial Grade; ComponentAvailability: Not for New Design
footprint PC84_N (Leaded Chip Carrier, 84-Leads, Body 29.3x29.3mm, Pitch 1.27mm, IPC Medium Density)
footprint PC84_L (Leaded Chip Carrier, 84-Leads, Body 29.3x29.3mm, Pitch 1.27mm, IPC High Density)
footprint PC84_M (Leaded Chip Carrier, 84-Leads, Body 29.3x29.3mm, Pitch 1.27mm, IPC Low Density)
3D model XC3130A-PC84 (84-Pin Plastic Leaded Chip Carrier (PC84))
pins: 1 GND (power), 2 A13-I/O (io), 3 A6-I/O (io), 4 A12-I/O (io), 5 A7-I/O (io), 6 NC, 7 NC, 8 A11-I/O (io), 9 A8-I/O (io), 10 A10-I/O (io), 11 A9-I/O (io), 12 ~{PWRDN} (in), 13 TCLKIN-I/O (io), 14 NC, 15 I/O (io), 16 I/O (io), 17 I/O (io), 18 I/O (io), 19 I/O (io), 20 I/O (io), 21 I/O (io), 22 VCC (power), 23 I/O (io), 24 I/O (io), 25 I/O (io), 26 I/O (io), 27 I/O (io), 28 I/O (io), 29 I/O (io), 30 I/O (io), 31 M1-~{RDATA} (out), 32 M0-RTRIG (in), 33 M2-I/O (io), 34 HDC-I/O (io), 35 I/O (io), 36 ~{LDC}-I/O (io), 37 I/O (io), 38 NC, 39 I/O (io), 40 I/O (io), 41 NC, 42 ~{INIT}-I/O (io), 43 GND (power), 44 I/O (io), 45 I/O (io), 46 I/O (io), 47 I/O (io), 48 I/O (io), 49 I/O (io), 50 NC, 51 NC, 52 I/O (io), 53 XTL2 (IN)-I/O (io), 54 ~{RESET} (in), 55 DONE-~{PROG} (out), 56 D7-I/O (io), 57 XTL1(OUT)-BCLKIN-I/O (io), 58 D6-I/O (io), 59 I/O (io), 60 D5-I/O (io), 61 ~{CS}0-I/O (io), 62 D4-I/O (io), 63 I/O (io), 64 VCC (power), 65 D3-I/O (io), 66 ~{CS}1-I/O (io), 67 D2-I/O (io), 68 I/O (io), 69 NC, 70 D1-I/O (io), 71 RDY/~{BUSY}-~{RCLK}-I/O (io), 72 DO-DIN-I/O (io), 73 DOUT-I/O (io), 74 CCLK (io), 75 A0-~{WS}-I/O (io), 76 A1-CS2-I/O (io), 77 A2-I/O (io), 78 A3-I/O (io), 79 NC, 80 NC, 81 A15-I/O (io), 82 A4-I/O (io), 83 A14-I/O (io), 84 A5-I/O (io)

## XC3130A-2PC84I
designator U?
Logic Cell Array with 100 CLBs, with 64 I/O Pins, 84-Pin PLCC, Industrial Grade; ComponentAvailability: Not for New Design
footprint PC84_N (Leaded Chip Carrier, 84-Leads, Body 29.3x29.3mm, Pitch 1.27mm, IPC Medium Density)
footprint PC84_L (Leaded Chip Carrier, 84-Leads, Body 29.3x29.3mm, Pitch 1.27mm, IPC High Density)
footprint PC84_M (Leaded Chip Carrier, 84-Leads, Body 29.3x29.3mm, Pitch 1.27mm, IPC Low Density)
3D model XC3130A-PC84 (84-Pin Plastic Leaded Chip Carrier (PC84))
pins: 1 GND (power), 2 A13-I/O (io), 3 A6-I/O (io), 4 A12-I/O (io), 5 A7-I/O (io), 6 NC, 7 NC, 8 A11-I/O (io), 9 A8-I/O (io), 10 A10-I/O (io), 11 A9-I/O (io), 12 ~{PWRDN} (in), 13 TCLKIN-I/O (io), 14 NC, 15 I/O (io), 16 I/O (io), 17 I/O (io), 18 I/O (io), 19 I/O (io), 20 I/O (io), 21 I/O (io), 22 VCC (power), 23 I/O (io), 24 I/O (io), 25 I/O (io), 26 I/O (io), 27 I/O (io), 28 I/O (io), 29 I/O (io), 30 I/O (io), 31 M1-~{RDATA} (out), 32 M0-RTRIG (in), 33 M2-I/O (io), 34 HDC-I/O (io), 35 I/O (io), 36 ~{LDC}-I/O (io), 37 I/O (io), 38 NC, 39 I/O (io), 40 I/O (io), 41 NC, 42 ~{INIT}-I/O (io), 43 GND (power), 44 I/O (io), 45 I/O (io), 46 I/O (io), 47 I/O (io), 48 I/O (io), 49 I/O (io), 50 NC, 51 NC, 52 I/O (io), 53 XTL2 (IN)-I/O (io), 54 ~{RESET} (in), 55 DONE-~{PROG} (out), 56 D7-I/O (io), 57 XTL1(OUT)-BCLKIN-I/O (io), 58 D6-I/O (io), 59 I/O (io), 60 D5-I/O (io), 61 ~{CS}0-I/O (io), 62 D4-I/O (io), 63 I/O (io), 64 VCC (power), 65 D3-I/O (io), 66 ~{CS}1-I/O (io), 67 D2-I/O (io), 68 I/O (io), 69 NC, 70 D1-I/O (io), 71 RDY/~{BUSY}-~{RCLK}-I/O (io), 72 DO-DIN-I/O (io), 73 DOUT-I/O (io), 74 CCLK (io), 75 A0-~{WS}-I/O (io), 76 A1-CS2-I/O (io), 77 A2-I/O (io), 78 A3-I/O (io), 79 NC, 80 NC, 81 A15-I/O (io), 82 A4-I/O (io), 83 A14-I/O (io), 84 A5-I/O (io)

## XC3130A-2PG84C
designator U?
Logic Cell Array with 100 CLBs, with 64 I/O Pins, 84-Pin PGA, Commercial Grade; ComponentAvailability: Not for New Design
footprint PG84 (PGA, 85-Leads, Body 28x28mm, Pitch 2.54mm)
3D model XC3130A-PG84 (84-Pin Ceramic Pin Grid Array (PG84))
pins: A1 A9-I/O (io), A2 A8-I/O (io), A3 A11-I/O (io), A4 NC, A5 A6-I/O (io), A6 A13-I/O (io), A7 A14-I/O (io), A8 NC, A9 A3-I/O (io), A10 A2-I/O (io), A11 CCLK (io), B1 NC, B2 ~{PWRDN} (in), B3 A10-I/O (io), B4 NC, B5 A12-I/O (io), B6 A15-I/O (io), B7 A4-I/O (io), B8 NC, B9 A1-CS2-I/O (io), B10 A0~{-WS}-I/O (io), B11 D0-DIN-I/O (io), C1 I/O (io), C2 TCLKIN-I/O (io), C5 A7-I/O (io), C6 GND (power), C7 A5-I/O (io), C10 DOUT-I/O (io), C11 RDY~{/BUSY}-~{RCLK}-I/O (io), D1 I/O (io), D2 I/O (io), D10 D1-I/O (io), D11 NC, E1 I/O (io), E2 I/O (io), E3 I/O (io), E9 I/O (io), E10 D2-I/O (io), E11 ~{CS}1-I/O (io), F1 I/O (io), F2 I/O (io), F3 VCC (power), F9 VCC (power), F10 D5-I/O (io), F11 D3-I/O (io), G1 I/O (io), G2 I/O (io), G3 I/O (io), G9 I/O (io), G10 ~{CS}0-I/O (io), G11 D4-I/O (io), H1 I/O (io), H2 I/O (io), H10 D6-I/O (io), H11 I/O (io), J1 I/O (io), J2 M1~{-RDATA} (out), J5 I/O (io), J6 GND (power), J7 I/O (io), J10 DONE-~{PROG} (out), J11 XTL1(OUT)-BLKIN-I/O (io), K1 I/O (io), K2 M2-I/O (io), K3 HDC-I/O (io), K4 I/O (io), K5 I/O (io), K6 ~{INIT}-I/O (io), K7 I/O (io), K8 I/O (io), K9 I/O (io), K10 ~{RESET} (in), K11 D7-I/O (io), L1 M0-RTRIG (in), L2 I/O (io), L3 ~{LDC}-I/O (io), L4 NC, L5 NC, L6 I/O (io), L7 I/O (io), L8 I/O (io), L9 NC, L10 NC, L11 XTL2(IN) -I/O (io)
